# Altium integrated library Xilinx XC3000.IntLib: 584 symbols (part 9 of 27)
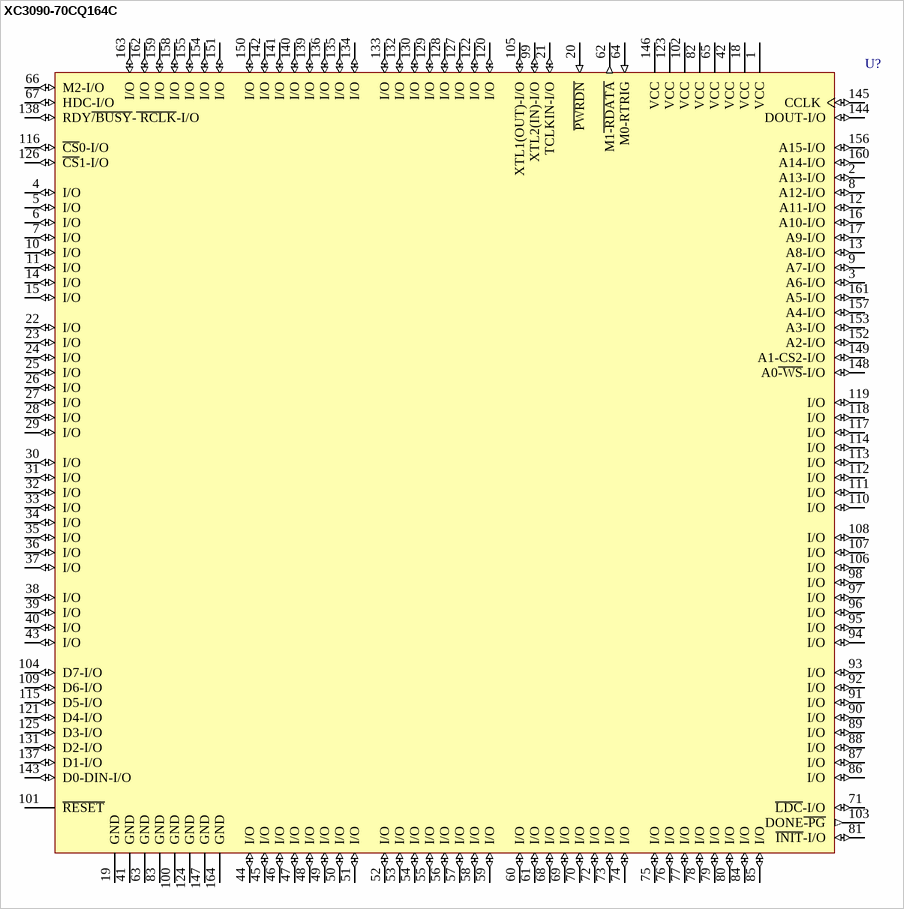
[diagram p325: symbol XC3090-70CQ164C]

## XC3090-70CQ164C
designator U?
Logic Cell Array with 320 CLBs, with 142 I/O Pins, 164-Pin CQFP, Commercial Grade; ComponentAvailability: Not for New Design
footprint CB164_N (CQFP, 164-Leads, Body 29x29mm; Pitch 0.635mm, Gullwing Leadform, IPC Medium Density)
footprint CB164_L (CQFP, 164-Leads, Body 29x29mm; Pitch 0.635mm, Gullwing Leadform, IPC High Density)
footprint CB164_M (CQFP, 164-Leads, Body 29x29mm; Pitch 0.635mm, Gullwing Leadform, IPC Low Density)
3D model XC3090-CB164 (164-Pin Ceramic Brazed Quad Flat Pack (CB164))
pins: 1 VCC (power), 2 A13-I/O (io), 3 A6-I/O (io), 4 I/O (io), 5 I/O (io), 6 I/O (io), 7 I/O (io), 8 A12-I/O (io), 9 A7-I/O (io), 10 I/O (io), 11 I/O (io), 12 A11-I/O (io), 13 A8-I/O (io), 14 I/O (io), 15 I/O (io), 16 A10-I/O (io), 17 A9-I/O (io), 18 VCC (power), 19 GND (power), 20 ~{PWRDN} (in), 21 TCLKIN-I/O (io), 22 I/O (io), 23 I/O (io), 24 I/O (io), 25 I/O (io), 26 I/O (io), 27 I/O (io), 28 I/O (io), 29 I/O (io), 30 I/O (io), 31 I/O (io), 32 I/O (io), 33 I/O (io), 34 I/O (io), 35 I/O (io), 36 I/O (io), 37 I/O (io), 38 I/O (io), 39 I/O (io), 40 I/O (io), 41 GND (power), 42 VCC (power), 43 I/O (io), 44 I/O (io), 45 I/O (io), 46 I/O (io), 47 I/O (io), 48 I/O (io), 49 I/O (io), 50 I/O (io), 51 I/O (io), 52 I/O (io), 53 I/O (io), 54 I/O (io), 55 I/O (io), 56 I/O (io), 57 I/O (io), 58 I/O (io), 59 I/O (io), 60 I/O (io), 61 I/O (io), 62 M1~{-RDATA} (out), 63 GND (power), 64 M0-RTRIG (in), 65 VCC (power), 66 M2-I/O (io), 67 HDC-I/O (io), 68 I/O (io), 69 I/O (io), 70 I/O (io), 71 ~{LDC}-I/O (io), 72 I/O (io), 73 I/O (io), 74 I/O (io), 75 I/O (io), 76 I/O (io), 77 I/O (io), 78 I/O (io), 79 I/O (io), 80 I/O (io), 81 ~{INIT}-I/O (io), 82 VCC (power), 83 GND (power), 84 I/O (io), 85 I/O (io), 86 I/O (io), 87 I/O (io), 88 I/O (io), 89 I/O (io), 90 I/O (io), 91 I/O (io), 92 I/O (io), 93 I/O (io), 94 I/O (io), 95 I/O (io), 96 I/O (io), 97 I/O (io), 98 I/O (io), 99 XTL2(IN)-I/O (io), 100 GND (power), 101 ~{RESET} (oe), 102 VCC (power), 103 DONE~{-PG} (out), 104 D7-I/O (io), 105 XTL1(OUT)-I/O (io), 106 I/O (io), 107 I/O (io), 108 I/O (io), 109 D6-I/O (io), 110 I/O (io), 111 I/O (io), 112 I/O (io), 113 I/O (io), 114 I/O (io), 115 D5-I/O (io), 116 ~{CS}0-I/O (io), 117 I/O (io), 118 I/O (io), 119 I/O (io), 120 I/O (io), 121 D4-I/O (io), 122 I/O (io), 123 VCC (power), 124 GND (power), 125 D3-I/O (io), 126 ~{CS}1-I/O (io), 127 I/O (io), 128 I/O (io), 129 I/O (io), 130 I/O (io), 131 D2-I/O (io), 132 I/O (io), 133 I/O (io), 134 I/O (io), 135 I/O (io), 136 I/O (io), 137 D1-I/O (io), 138 RDY~{/BUSY}-~{ RCLK}-I/O (io), 139 I/O (io), 140 I/O (io), 141 I/O (io), 142 I/O (io), 143 D0-DIN-I/O (io), 144 DOUT-I/O (io), 145 CCLK (io), 146 VCC (power), 147 GND (power), 148 A0~{-WS}-I/O (io), 149 A1-CS2-I/O (io), 150 I/O (io), 151 I/O (io), 152 A2-I/O (io), 153 A3-I/O (io), 154 I/O (io), 155 I/O (io), 156 A15-I/O (io), 157 A4-I/O (io), 158 I/O (io), 159 I/O (io), 160 A14-I/O (io), 161 A5-I/O (io), 162 I/O (io), 163 I/O (io), 164 GND (power)

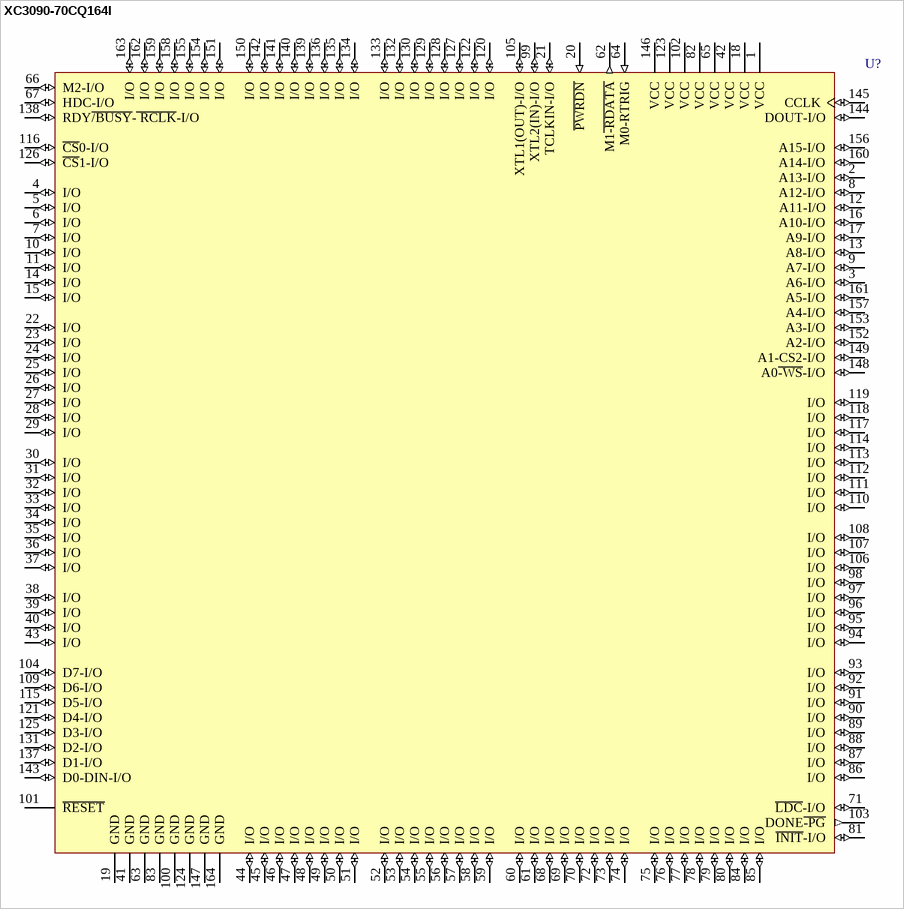
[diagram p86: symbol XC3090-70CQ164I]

## XC3090-70CQ164I
designator U?
Logic Cell Array with 320 CLBs, with 142 I/O Pins, 164-Pin CQFP, Industrial Grade; ComponentAvailability: Not for New Design
footprint CB164_N (CQFP, 164-Leads, Body 29x29mm; Pitch 0.635mm, Gullwing Leadform, IPC Medium Density)
footprint CB164_L (CQFP, 164-Leads, Body 29x29mm; Pitch 0.635mm, Gullwing Leadform, IPC High Density)
footprint CB164_M (CQFP, 164-Leads, Body 29x29mm; Pitch 0.635mm, Gullwing Leadform, IPC Low Density)
3D model XC3090-CB164 (164-Pin Ceramic Brazed Quad Flat Pack (CB164))
pins: 1 VCC (power), 2 A13-I/O (io), 3 A6-I/O (io), 4 I/O (io), 5 I/O (io), 6 I/O (io), 7 I/O (io), 8 A12-I/O (io), 9 A7-I/O (io), 10 I/O (io), 11 I/O (io), 12 A11-I/O (io), 13 A8-I/O (io), 14 I/O (io), 15 I/O (io), 16 A10-I/O (io), 17 A9-I/O (io), 18 VCC (power), 19 GND (power), 20 ~{PWRDN} (in), 21 TCLKIN-I/O (io), 22 I/O (io), 23 I/O (io), 24 I/O (io), 25 I/O (io), 26 I/O (io), 27 I/O (io), 28 I/O (io), 29 I/O (io), 30 I/O (io), 31 I/O (io), 32 I/O (io), 33 I/O (io), 34 I/O (io), 35 I/O (io), 36 I/O (io), 37 I/O (io), 38 I/O (io), 39 I/O (io), 40 I/O (io), 41 GND (power), 42 VCC (power), 43 I/O (io), 44 I/O (io), 45 I/O (io), 46 I/O (io), 47 I/O (io), 48 I/O (io), 49 I/O (io), 50 I/O (io), 51 I/O (io), 52 I/O (io), 53 I/O (io), 54 I/O (io), 55 I/O (io), 56 I/O (io), 57 I/O (io), 58 I/O (io), 59 I/O (io), 60 I/O (io), 61 I/O (io), 62 M1~{-RDATA} (out), 63 GND (power), 64 M0-RTRIG (in), 65 VCC (power), 66 M2-I/O (io), 67 HDC-I/O (io), 68 I/O (io), 69 I/O (io), 70 I/O (io), 71 ~{LDC}-I/O (io), 72 I/O (io), 73 I/O (io), 74 I/O (io), 75 I/O (io), 76 I/O (io), 77 I/O (io), 78 I/O (io), 79 I/O (io), 80 I/O (io), 81 ~{INIT}-I/O (io), 82 VCC (power), 83 GND (power), 84 I/O (io), 85 I/O (io), 86 I/O (io), 87 I/O (io), 88 I/O (io), 89 I/O (io), 90 I/O (io), 91 I/O (io), 92 I/O (io), 93 I/O (io), 94 I/O (io), 95 I/O (io), 96 I/O (io), 97 I/O (io), 98 I/O (io), 99 XTL2(IN)-I/O (io), 100 GND (power), 101 ~{RESET} (oe), 102 VCC (power), 103 DONE~{-PG} (out), 104 D7-I/O (io), 105 XTL1(OUT)-I/O (io), 106 I/O (io), 107 I/O (io), 108 I/O (io), 109 D6-I/O (io), 110 I/O (io), 111 I/O (io), 112 I/O (io), 113 I/O (io), 114 I/O (io), 115 D5-I/O (io), 116 ~{CS}0-I/O (io), 117 I/O (io), 118 I/O (io), 119 I/O (io), 120 I/O (io), 121 D4-I/O (io), 122 I/O (io), 123 VCC (power), 124 GND (power), 125 D3-I/O (io), 126 ~{CS}1-I/O (io), 127 I/O (io), 128 I/O (io), 129 I/O (io), 130 I/O (io), 131 D2-I/O (io), 132 I/O (io), 133 I/O (io), 134 I/O (io), 135 I/O (io), 136 I/O (io), 137 D1-I/O (io), 138 RDY~{/BUSY}-~{ RCLK}-I/O (io), 139 I/O (io), 140 I/O (io), 141 I/O (io), 142 I/O (io), 143 D0-DIN-I/O (io), 144 DOUT-I/O (io), 145 CCLK (io), 146 VCC (power), 147 GND (power), 148 A0~{-WS}-I/O (io), 149 A1-CS2-I/O (io), 150 I/O (io), 151 I/O (io), 152 A2-I/O (io), 153 A3-I/O (io), 154 I/O (io), 155 I/O (io), 156 A15-I/O (io), 157 A4-I/O (io), 158 I/O (io), 159 I/O (io), 160 A14-I/O (io), 161 A5-I/O (io), 162 I/O (io), 163 I/O (io), 164 GND (power)

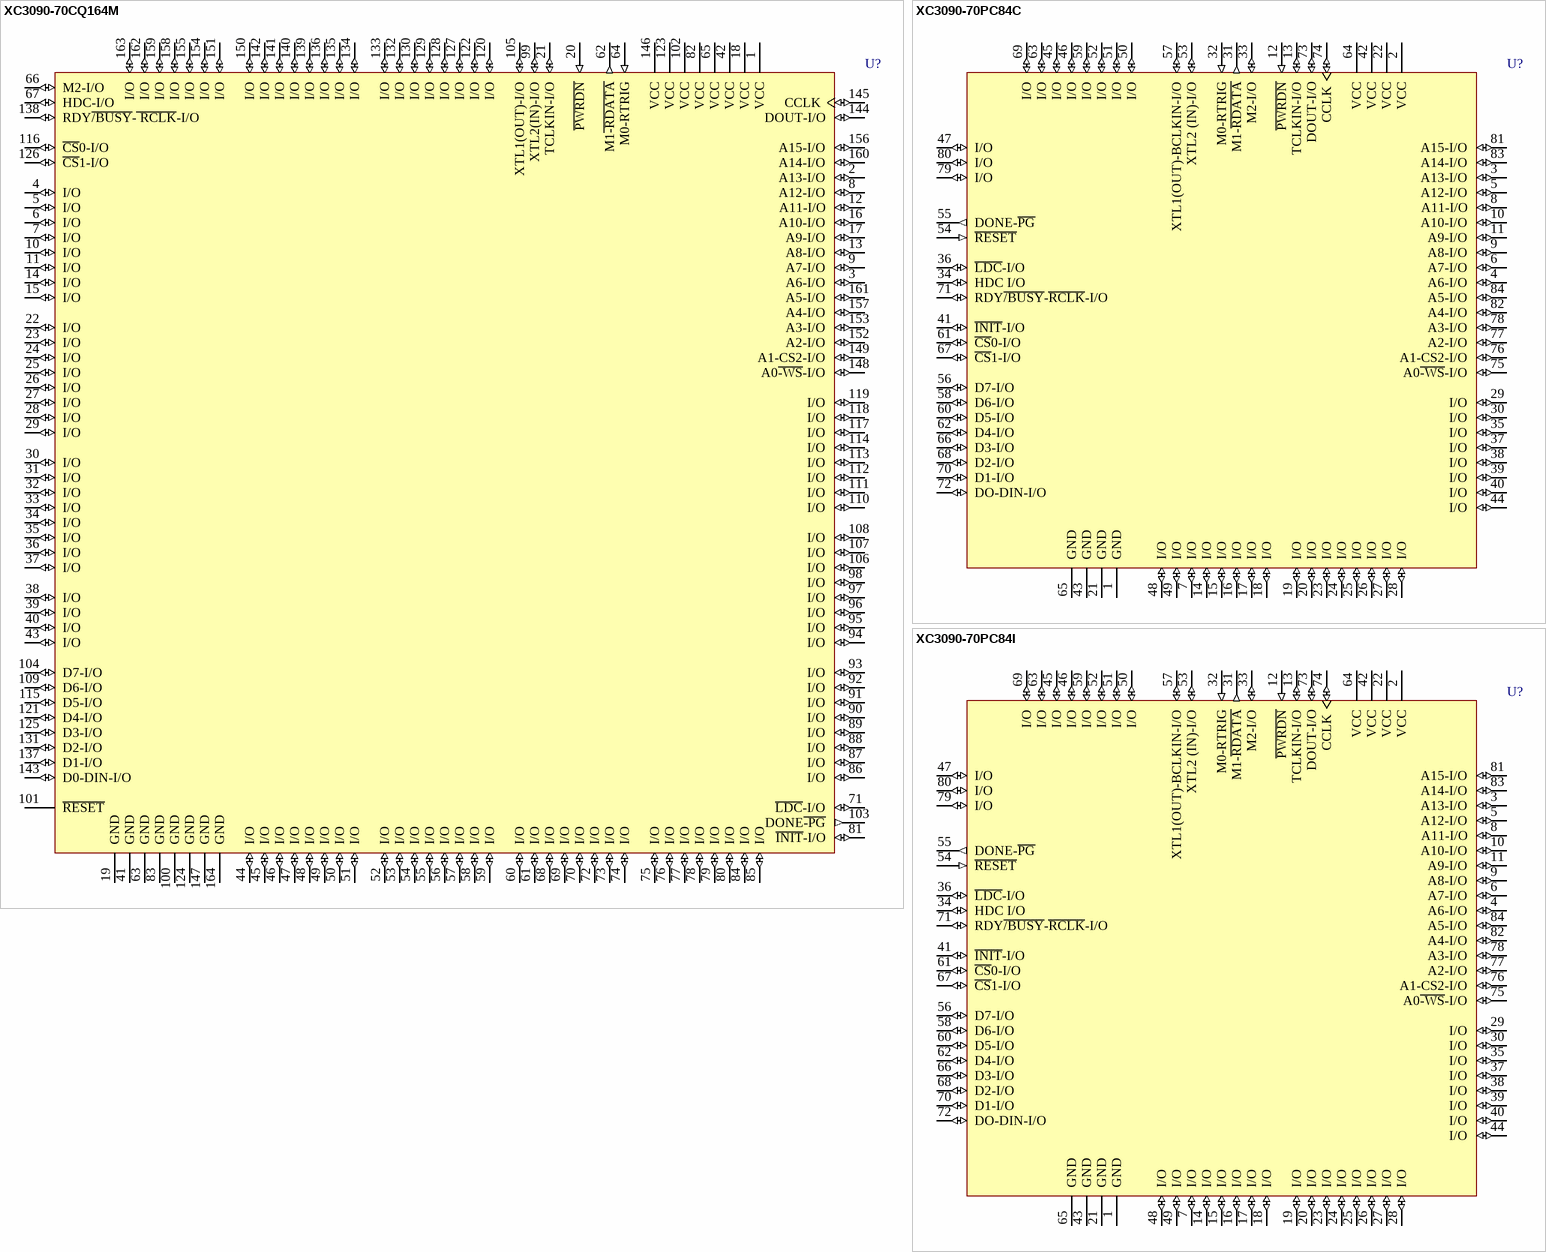
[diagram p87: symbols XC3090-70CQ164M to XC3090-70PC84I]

## XC3090-70CQ164M
designator U?
Logic Cell Array with 320 CLBs, with 142 I/O Pins, 164-Pin CQFP, Military Grade; ComponentAvailability: Not for New Design
footprint CB164_N (CQFP, 164-Leads, Body 29x29mm; Pitch 0.635mm, Gullwing Leadform, IPC Medium Density)
footprint CB164_L (CQFP, 164-Leads, Body 29x29mm; Pitch 0.635mm, Gullwing Leadform, IPC High Density)
footprint CB164_M (CQFP, 164-Leads, Body 29x29mm; Pitch 0.635mm, Gullwing Leadform, IPC Low Density)
3D model XC3090-CB164 (164-Pin Ceramic Brazed Quad Flat Pack (CB164))
pins: 1 VCC (power), 2 A13-I/O (io), 3 A6-I/O (io), 4 I/O (io), 5 I/O (io), 6 I/O (io), 7 I/O (io), 8 A12-I/O (io), 9 A7-I/O (io), 10 I/O (io), 11 I/O (io), 12 A11-I/O (io), 13 A8-I/O (io), 14 I/O (io), 15 I/O (io), 16 A10-I/O (io), 17 A9-I/O (io), 18 VCC (power), 19 GND (power), 20 ~{PWRDN} (in), 21 TCLKIN-I/O (io), 22 I/O (io), 23 I/O (io), 24 I/O (io), 25 I/O (io), 26 I/O (io), 27 I/O (io), 28 I/O (io), 29 I/O (io), 30 I/O (io), 31 I/O (io), 32 I/O (io), 33 I/O (io), 34 I/O (io), 35 I/O (io), 36 I/O (io), 37 I/O (io), 38 I/O (io), 39 I/O (io), 40 I/O (io), 41 GND (power), 42 VCC (power), 43 I/O (io), 44 I/O (io), 45 I/O (io), 46 I/O (io), 47 I/O (io), 48 I/O (io), 49 I/O (io), 50 I/O (io), 51 I/O (io), 52 I/O (io), 53 I/O (io), 54 I/O (io), 55 I/O (io), 56 I/O (io), 57 I/O (io), 58 I/O (io), 59 I/O (io), 60 I/O (io), 61 I/O (io), 62 M1~{-RDATA} (out), 63 GND (power), 64 M0-RTRIG (in), 65 VCC (power), 66 M2-I/O (io), 67 HDC-I/O (io), 68 I/O (io), 69 I/O (io), 70 I/O (io), 71 ~{LDC}-I/O (io), 72 I/O (io), 73 I/O (io), 74 I/O (io), 75 I/O (io), 76 I/O (io), 77 I/O (io), 78 I/O (io), 79 I/O (io), 80 I/O (io), 81 ~{INIT}-I/O (io), 82 VCC (power), 83 GND (power), 84 I/O (io), 85 I/O (io), 86 I/O (io), 87 I/O (io), 88 I/O (io), 89 I/O (io), 90 I/O (io), 91 I/O (io), 92 I/O (io), 93 I/O (io), 94 I/O (io), 95 I/O (io), 96 I/O (io), 97 I/O (io), 98 I/O (io), 99 XTL2(IN)-I/O (io), 100 GND (power), 101 ~{RESET} (oe), 102 VCC (power), 103 DONE~{-PG} (out), 104 D7-I/O (io), 105 XTL1(OUT)-I/O (io), 106 I/O (io), 107 I/O (io), 108 I/O (io), 109 D6-I/O (io), 110 I/O (io), 111 I/O (io), 112 I/O (io), 113 I/O (io), 114 I/O (io), 115 D5-I/O (io), 116 ~{CS}0-I/O (io), 117 I/O (io), 118 I/O (io), 119 I/O (io), 120 I/O (io), 121 D4-I/O (io), 122 I/O (io), 123 VCC (power), 124 GND (power), 125 D3-I/O (io), 126 ~{CS}1-I/O (io), 127 I/O (io), 128 I/O (io), 129 I/O (io), 130 I/O (io), 131 D2-I/O (io), 132 I/O (io), 133 I/O (io), 134 I/O (io), 135 I/O (io), 136 I/O (io), 137 D1-I/O (io), 138 RDY~{/BUSY}-~{ RCLK}-I/O (io), 139 I/O (io), 140 I/O (io), 141 I/O (io), 142 I/O (io), 143 D0-DIN-I/O (io), 144 DOUT-I/O (io), 145 CCLK (io), 146 VCC (power), 147 GND (power), 148 A0~{-WS}-I/O (io), 149 A1-CS2-I/O (io), 150 I/O (io), 151 I/O (io), 152 A2-I/O (io), 153 A3-I/O (io), 154 I/O (io), 155 I/O (io), 156 A15-I/O (io), 157 A4-I/O (io), 158 I/O (io), 159 I/O (io), 160 A14-I/O (io), 161 A5-I/O (io), 162 I/O (io), 163 I/O (io), 164 GND (power)

## XC3090-70PC84C
designator U?
Logic Cell Array with 320 CLBs, with 70 I/O Pins, 84-Pin PLCC, Commercial Grade; ComponentAvailability: Not for New Design
footprint PC84_N (Leaded Chip Carrier, 84-Leads, Body 29.3x29.3mm, Pitch 1.27mm, IPC Medium Density)
footprint PC84_L (Leaded Chip Carrier, 84-Leads, Body 29.3x29.3mm, Pitch 1.27mm, IPC High Density)
footprint PC84_M (Leaded Chip Carrier, 84-Leads, Body 29.3x29.3mm, Pitch 1.27mm, IPC Low Density)
3D model XC3090-PC84 (84-Pin Plastic Leaded Chip Carrier (PC84))
pins: 1 GND (power), 2 VCC (power), 3 A13-I/O (io), 4 A6-I/O (io), 5 A12-I/O (io), 6 A7-I/O (io), 7 I/O (io), 8 A11-I/O (io), 9 A8-I/O (io), 10 A10-I/O (io), 11 A9-I/O (io), 12 ~{PWRDN} (in), 13 TCLKIN-I/O (io), 14 I/O (io), 15 I/O (io), 16 I/O (io), 17 I/O (io), 18 I/O (io), 19 I/O (io), 20 I/O (io), 21 GND (power), 22 VCC (power), 23 I/O (io), 24 I/O (io), 25 I/O (io), 26 I/O (io), 27 I/O (io), 28 I/O (io), 29 I/O (io), 30 I/O (io), 31 M1-~{RDATA} (out), 32 M0-RTRIG (in), 33 M2-I/O (io), 34 HDC I/O (io), 35 I/O (io), 36 ~{LDC}-I/O (io), 37 I/O (io), 38 I/O (io), 39 I/O (io), 40 I/O (io), 41 ~{INIT}-I/O (io), 42 VCC (power), 43 GND (power), 44 I/O (io), 45 I/O (io), 46 I/O (io), 47 I/O (io), 48 I/O (io), 49 I/O (io), 50 I/O (io), 51 I/O (io), 52 I/O (io), 53 XTL2 (IN)-I/O (io), 54 ~{RESET} (in), 55 DONE-~{PG} (out), 56 D7-I/O (io), 57 XTL1(OUT)-BCLKIN-I/O (io), 58 D6-I/O (io), 59 I/O (io), 60 D5-I/O (io), 61 ~{CS}0-I/O (io), 62 D4-I/O (io), 63 I/O (io), 64 VCC (power), 65 GND (power), 66 D3-I/O (io), 67 ~{CS}1-I/O (io), 68 D2-I/O (io), 69 I/O (io), 70 D1-I/O (io), 71 RDY~{/BUSY}-~{RCLK}-I/O (io), 72 DO-DIN-I/O (io), 73 DOUT-I/O (io), 74 CCLK (io), 75 A0~{-WS}-I/O (io), 76 A1-CS2-I/O (io), 77 A2-I/O (io), 78 A3-I/O (io), 79 I/O (io), 80 I/O (io), 81 A15-I/O (io), 82 A4-I/O (io), 83 A14-I/O (io), 84 A5-I/O (io)

## XC3090-70PC84I
designator U?
Logic Cell Array with 320 CLBs, with 70 I/O Pins, 84-Pin PLCC, Industrial Grade; ComponentAvailability: Not for New Design
footprint PC84_N (Leaded Chip Carrier, 84-Leads, Body 29.3x29.3mm, Pitch 1.27mm, IPC Medium Density)
footprint PC84_L (Leaded Chip Carrier, 84-Leads, Body 29.3x29.3mm, Pitch 1.27mm, IPC High Density)
footprint PC84_M (Leaded Chip Carrier, 84-Leads, Body 29.3x29.3mm, Pitch 1.27mm, IPC Low Density)
3D model XC3090-PC84 (84-Pin Plastic Leaded Chip Carrier (PC84))
pins: 1 GND (power), 2 VCC (power), 3 A13-I/O (io), 4 A6-I/O (io), 5 A12-I/O (io), 6 A7-I/O (io), 7 I/O (io), 8 A11-I/O (io), 9 A8-I/O (io), 10 A10-I/O (io), 11 A9-I/O (io), 12 ~{PWRDN} (in), 13 TCLKIN-I/O (io), 14 I/O (io), 15 I/O (io), 16 I/O (io), 17 I/O (io), 18 I/O (io), 19 I/O (io), 20 I/O (io), 21 GND (power), 22 VCC (power), 23 I/O (io), 24 I/O (io), 25 I/O (io), 26 I/O (io), 27 I/O (io), 28 I/O (io), 29 I/O (io), 30 I/O (io), 31 M1-~{RDATA} (out), 32 M0-RTRIG (in), 33 M2-I/O (io), 34 HDC I/O (io), 35 I/O (io), 36 ~{LDC}-I/O (io), 37 I/O (io), 38 I/O (io), 39 I/O (io), 40 I/O (io), 41 ~{INIT}-I/O (io), 42 VCC (power), 43 GND (power), 44 I/O (io), 45 I/O (io), 46 I/O (io), 47 I/O (io), 48 I/O (io), 49 I/O (io), 50 I/O (io), 51 I/O (io), 52 I/O (io), 53 XTL2 (IN)-I/O (io), 54 ~{RESET} (in), 55 DONE-~{PG} (out), 56 D7-I/O (io), 57 XTL1(OUT)-BCLKIN-I/O (io), 58 D6-I/O (io), 59 I/O (io), 60 D5-I/O (io), 61 ~{CS}0-I/O (io), 62 D4-I/O (io), 63 I/O (io), 64 VCC (power), 65 GND (power), 66 D3-I/O (io), 67 ~{CS}1-I/O (io), 68 D2-I/O (io), 69 I/O (io), 70 D1-I/O (io), 71 RDY~{/BUSY}-~{RCLK}-I/O (io), 72 DO-DIN-I/O (io), 73 DOUT-I/O (io), 74 CCLK (io), 75 A0~{-WS}-I/O (io), 76 A1-CS2-I/O (io), 77 A2-I/O (io), 78 A3-I/O (io), 79 I/O (io), 80 I/O (io), 81 A15-I/O (io), 82 A4-I/O (io), 83 A14-I/O (io), 84 A5-I/O (io)

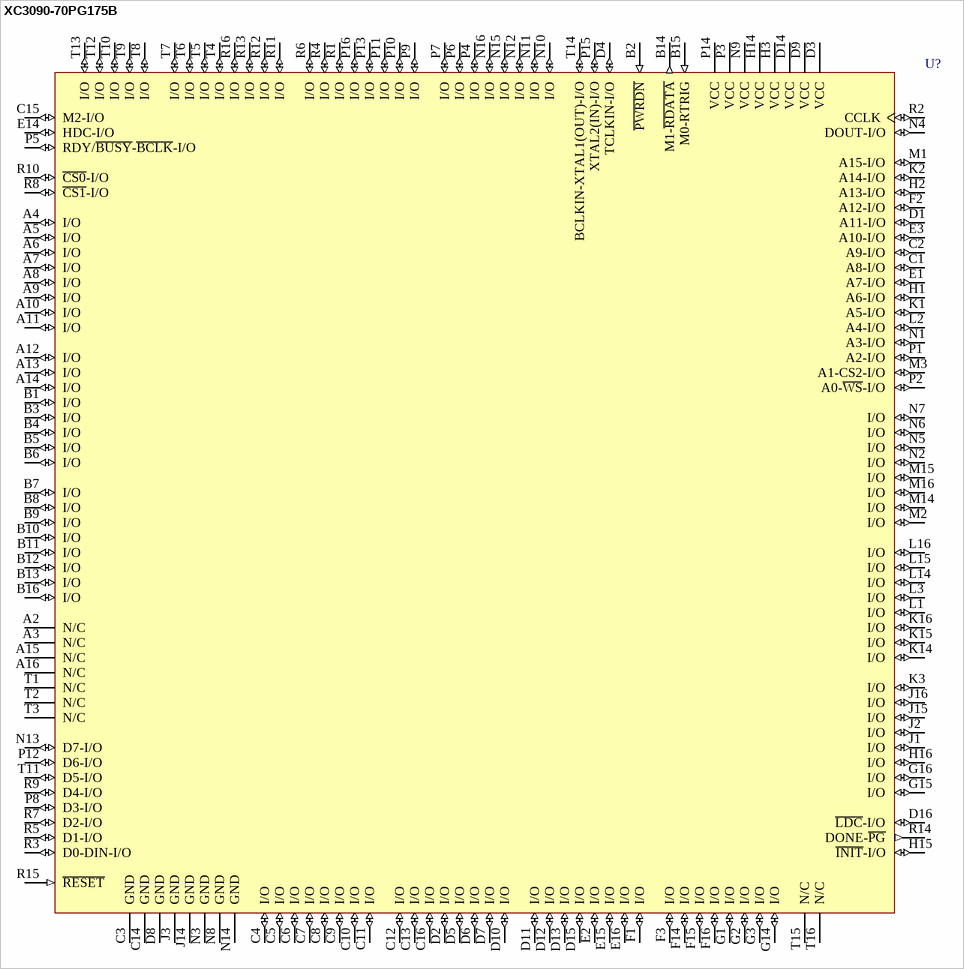
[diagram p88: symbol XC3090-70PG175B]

## XC3090-70PG175B
designator U?
Logic Cell Array with 320 CLBs, with 144 I/O Pins, 175-Pin PGA, Military Class B Grade; ComponentAvailability: Not for New Design
footprint PG175 (PGA, 175-Leads, Body 42x42mm, Pitch 2.54mm)
3D model XC3090-PG175 (175-Pin Ceramic Pin Grid Array (PG175))
pins: A2 N/C, A3 N/C, A4 I/O (io), A5 I/O (io), A6 I/O (io), A7 I/O (io), A8 I/O (io), A9 I/O (io), A10 I/O (io), A11 I/O (io), A12 I/O (io), A13 I/O (io), A14 I/O (io), A15 N/C, A16 N/C, B1 I/O (io), B2 ~{PWRDN} (in), B3 I/O (io), B4 I/O (io), B5 I/O (io), B6 I/O (io), B7 I/O (io), B8 I/O (io), B9 I/O (io), B10 I/O (io), B11 I/O (io), B12 I/O (io), B13 I/O (io), B14 M1-~{RDATA} (out), B15 M0-RTRIG (in), B16 I/O (io), C1 A8-I/O (io), C2 A9-I/O (io), C3 GND (power), C4 I/O (io), C5 I/O (io), C6 I/O (io), C7 I/O (io), C8 I/O (io), C9 I/O (io), C10 I/O (io), C11 I/O (io), C12 I/O (io), C13 I/O (io), C14 GND (power), C15 M2-I/O (io), C16 I/O (io), D1 A11-I/O (io), D2 I/O (io), D3 VCC (power), D4 TCLKIN-I/O (io), D5 I/O (io), D6 I/O (io), D7 I/O (io), D8 GND (power), D9 VCC (power), D10 I/O (io), D11 I/O (io), D12 I/O (io), D13 I/O (io), D14 VCC (power), D15 I/O (io), D16 ~{LDC}-I/O (io), E1 A7-I/O (io), E2 I/O (io), E3 A10-I/O (io), E14 HDC-I/O (io), E15 I/O (io), E16 I/O (io), F1 I/O (io), F2 A12-I/O (io), F3 I/O (io), F14 I/O (io), F15 I/O (io), F16 I/O (io), G1 I/O (io), G2 I/O (io), G3 I/O (io), G14 I/O (io), G15 I/O (io), G16 I/O (io), H1 A6-I/O (io), H2 A13-I/O (io), H3 VCC (power), H14 VCC (power), H15 ~{INIT}-I/O (io), H16 I/O (io), J1 I/O (io), J2 I/O (io), J3 GND (power), J14 GND (power), J15 I/O (io), J16 I/O (io), K1 A5-I/O (io), K2 A14-I/O (io), K3 I/O (io), K14 I/O (io), K15 I/O (io), K16 I/O (io), L1 I/O (io), L2 A4-I/O (io), L3 I/O (io), L14 I/O (io), L15 I/O (io), L16 I/O (io), M1 A15-I/O (io), M2 I/O (io), M3 A1-CS2-I/O (io), M14 I/O (io), M15 I/O (io), M16 I/O (io), N1 A3-I/O (io), N2 I/O (io), N3 GND (power), N4 DOUT-I/O (io), N5 I/O (io), N6 I/O (io), N7 I/O (io), N8 GND (power), N9 VCC (power), N10 I/O (io), N11 I/O (io), N12 I/O (io), N13 D7-I/O (io), N14 GND (power), N15 I/O (io), N16 I/O (io), P1 A2-I/O (io), P2 A0-~{WS}-I/O (io), P3 VCC (power), P4 I/O (io), P5 RDY/~{BUSY}-~{BCLK}-I/O (io), P6 I/O (io), P7 I/O (io), P8 D3-I/O (io), P9 I/O (io), P10 I/O (io), P11 I/O (io), P12 D6-I/O (io), P13 I/O (io), P14 VCC (power), P15 XTAL2(IN)-I/O (io), P16 I/O (io), R1 I/O (io), R2 CCLK (io), R3 D0-DIN-I/O (io), R4 I/O (io), R5 D1-I/O (io), R6 I/O (io), R7 D2-I/O (io), R8 ~{CS1}-I/O (io), R9 D4-I/O (io), R10 ~{CS0}-I/O (io), R11 I/O (io), R12 I/O (io), R13 I/O (io), R14 DONE-~{PG} (out), R15 ~{RESET} (in), R16 I/O (io), T1 N/C, T2 N/C, T3 N/C, T4 I/O (io), T5 I/O (io), T6 I/O (io), T7 I/O (io), T8 I/O (io), T9 I/O (io), T10 I/O (io), T11 D5-I/O (io), T12 I/O (io), T13 I/O (io), T14 BCLKIN-XTAL1(OUT)-I/O (io), T15 N/C, T16 N/C

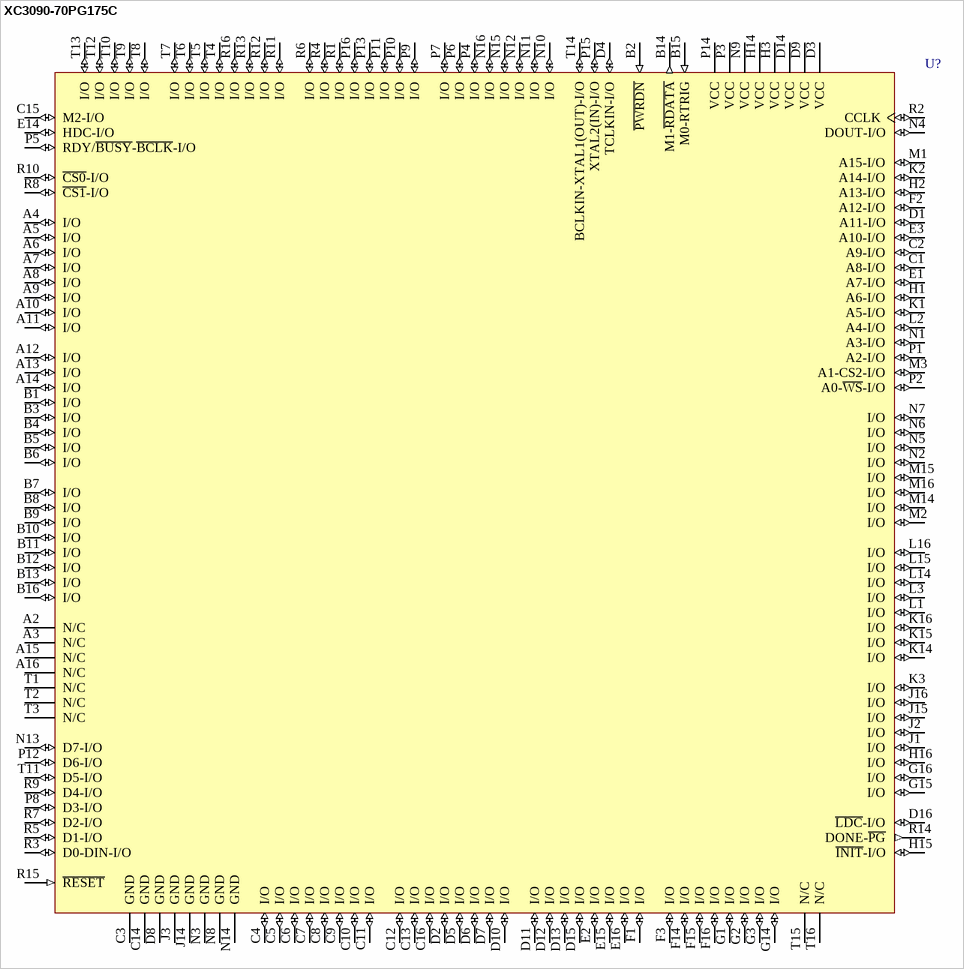
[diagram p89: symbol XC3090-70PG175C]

## XC3090-70PG175C
designator U?
Logic Cell Array with 320 CLBs, with 144 I/O Pins, 175-Pin PGA, Commercial Grade; ComponentAvailability: Not for New Design
footprint PG175 (PGA, 175-Leads, Body 42x42mm, Pitch 2.54mm)
3D model XC3090-PG175 (175-Pin Ceramic Pin Grid Array (PG175))
pins: A2 N/C, A3 N/C, A4 I/O (io), A5 I/O (io), A6 I/O (io), A7 I/O (io), A8 I/O (io), A9 I/O (io), A10 I/O (io), A11 I/O (io), A12 I/O (io), A13 I/O (io), A14 I/O (io), A15 N/C, A16 N/C, B1 I/O (io), B2 ~{PWRDN} (in), B3 I/O (io), B4 I/O (io), B5 I/O (io), B6 I/O (io), B7 I/O (io), B8 I/O (io), B9 I/O (io), B10 I/O (io), B11 I/O (io), B12 I/O (io), B13 I/O (io), B14 M1-~{RDATA} (out), B15 M0-RTRIG (in), B16 I/O (io), C1 A8-I/O (io), C2 A9-I/O (io), C3 GND (power), C4 I/O (io), C5 I/O (io), C6 I/O (io), C7 I/O (io), C8 I/O (io), C9 I/O (io), C10 I/O (io), C11 I/O (io), C12 I/O (io), C13 I/O (io), C14 GND (power), C15 M2-I/O (io), C16 I/O (io), D1 A11-I/O (io), D2 I/O (io), D3 VCC (power), D4 TCLKIN-I/O (io), D5 I/O (io), D6 I/O (io), D7 I/O (io), D8 GND (power), D9 VCC (power), D10 I/O (io), D11 I/O (io), D12 I/O (io), D13 I/O (io), D14 VCC (power), D15 I/O (io), D16 ~{LDC}-I/O (io), E1 A7-I/O (io), E2 I/O (io), E3 A10-I/O (io), E14 HDC-I/O (io), E15 I/O (io), E16 I/O (io), F1 I/O (io), F2 A12-I/O (io), F3 I/O (io), F14 I/O (io), F15 I/O (io), F16 I/O (io), G1 I/O (io), G2 I/O (io), G3 I/O (io), G14 I/O (io), G15 I/O (io), G16 I/O (io), H1 A6-I/O (io), H2 A13-I/O (io), H3 VCC (power), H14 VCC (power), H15 ~{INIT}-I/O (io), H16 I/O (io), J1 I/O (io), J2 I/O (io), J3 GND (power), J14 GND (power), J15 I/O (io), J16 I/O (io), K1 A5-I/O (io), K2 A14-I/O (io), K3 I/O (io), K14 I/O (io), K15 I/O (io), K16 I/O (io), L1 I/O (io), L2 A4-I/O (io), L3 I/O (io), L14 I/O (io), L15 I/O (io), L16 I/O (io), M1 A15-I/O (io), M2 I/O (io), M3 A1-CS2-I/O (io), M14 I/O (io), M15 I/O (io), M16 I/O (io), N1 A3-I/O (io), N2 I/O (io), N3 GND (power), N4 DOUT-I/O (io), N5 I/O (io), N6 I/O (io), N7 I/O (io), N8 GND (power), N9 VCC (power), N10 I/O (io), N11 I/O (io), N12 I/O (io), N13 D7-I/O (io), N14 GND (power), N15 I/O (io), N16 I/O (io), P1 A2-I/O (io), P2 A0-~{WS}-I/O (io), P3 VCC (power), P4 I/O (io), P5 RDY/~{BUSY}-~{BCLK}-I/O (io), P6 I/O (io), P7 I/O (io), P8 D3-I/O (io), P9 I/O (io), P10 I/O (io), P11 I/O (io), P12 D6-I/O (io), P13 I/O (io), P14 VCC (power), P15 XTAL2(IN)-I/O (io), P16 I/O (io), R1 I/O (io), R2 CCLK (io), R3 D0-DIN-I/O (io), R4 I/O (io), R5 D1-I/O (io), R6 I/O (io), R7 D2-I/O (io), R8 ~{CS1}-I/O (io), R9 D4-I/O (io), R10 ~{CS0}-I/O (io), R11 I/O (io), R12 I/O (io), R13 I/O (io), R14 DONE-~{PG} (out), R15 ~{RESET} (in), R16 I/O (io), T1 N/C, T2 N/C, T3 N/C, T4 I/O (io), T5 I/O (io), T6 I/O (io), T7 I/O (io), T8 I/O (io), T9 I/O (io), T10 I/O (io), T11 D5-I/O (io), T12 I/O (io), T13 I/O (io), T14 BCLKIN-XTAL1(OUT)-I/O (io), T15 N/C, T16 N/C

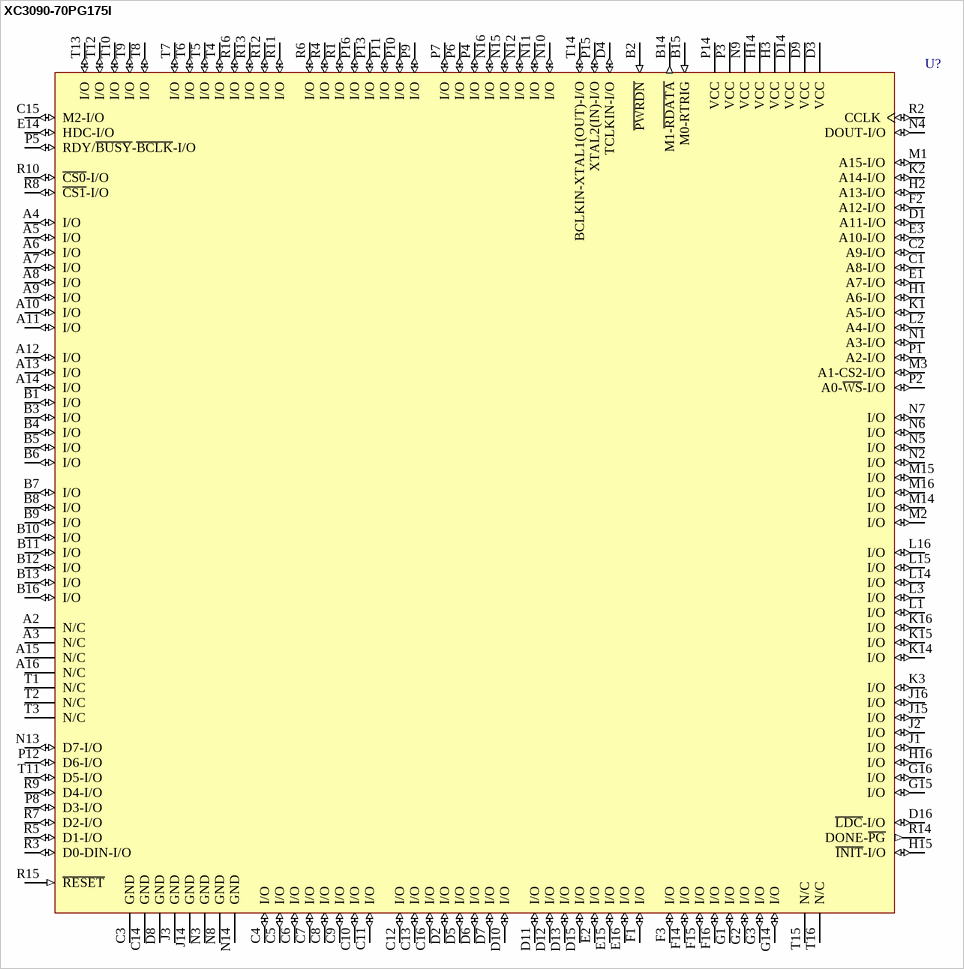
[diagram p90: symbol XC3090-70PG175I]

## XC3090-70PG175I
designator U?
Logic Cell Array with 320 CLBs, with 144 I/O Pins, 175-Pin PGA, Industrial Grade; ComponentAvailability: Not for New Design
footprint PG175 (PGA, 175-Leads, Body 42x42mm, Pitch 2.54mm)
3D model XC3090-PG175 (175-Pin Ceramic Pin Grid Array (PG175))
pins: A2 N/C, A3 N/C, A4 I/O (io), A5 I/O (io), A6 I/O (io), A7 I/O (io), A8 I/O (io), A9 I/O (io), A10 I/O (io), A11 I/O (io), A12 I/O (io), A13 I/O (io), A14 I/O (io), A15 N/C, A16 N/C, B1 I/O (io), B2 ~{PWRDN} (in), B3 I/O (io), B4 I/O (io), B5 I/O (io), B6 I/O (io), B7 I/O (io), B8 I/O (io), B9 I/O (io), B10 I/O (io), B11 I/O (io), B12 I/O (io), B13 I/O (io), B14 M1-~{RDATA} (out), B15 M0-RTRIG (in), B16 I/O (io), C1 A8-I/O (io), C2 A9-I/O (io), C3 GND (power), C4 I/O (io), C5 I/O (io), C6 I/O (io), C7 I/O (io), C8 I/O (io), C9 I/O (io), C10 I/O (io), C11 I/O (io), C12 I/O (io), C13 I/O (io), C14 GND (power), C15 M2-I/O (io), C16 I/O (io), D1 A11-I/O (io), D2 I/O (io), D3 VCC (power), D4 TCLKIN-I/O (io), D5 I/O (io), D6 I/O (io), D7 I/O (io), D8 GND (power), D9 VCC (power), D10 I/O (io), D11 I/O (io), D12 I/O (io), D13 I/O (io), D14 VCC (power), D15 I/O (io), D16 ~{LDC}-I/O (io), E1 A7-I/O (io), E2 I/O (io), E3 A10-I/O (io), E14 HDC-I/O (io), E15 I/O (io), E16 I/O (io), F1 I/O (io), F2 A12-I/O (io), F3 I/O (io), F14 I/O (io), F15 I/O (io), F16 I/O (io), G1 I/O (io), G2 I/O (io), G3 I/O (io), G14 I/O (io), G15 I/O (io), G16 I/O (io), H1 A6-I/O (io), H2 A13-I/O (io), H3 VCC (power), H14 VCC (power), H15 ~{INIT}-I/O (io), H16 I/O (io), J1 I/O (io), J2 I/O (io), J3 GND (power), J14 GND (power), J15 I/O (io), J16 I/O (io), K1 A5-I/O (io), K2 A14-I/O (io), K3 I/O (io), K14 I/O (io), K15 I/O (io), K16 I/O (io), L1 I/O (io), L2 A4-I/O (io), L3 I/O (io), L14 I/O (io), L15 I/O (io), L16 I/O (io), M1 A15-I/O (io), M2 I/O (io), M3 A1-CS2-I/O (io), M14 I/O (io), M15 I/O (io), M16 I/O (io), N1 A3-I/O (io), N2 I/O (io), N3 GND (power), N4 DOUT-I/O (io), N5 I/O (io), N6 I/O (io), N7 I/O (io), N8 GND (power), N9 VCC (power), N10 I/O (io), N11 I/O (io), N12 I/O (io), N13 D7-I/O (io), N14 GND (power), N15 I/O (io), N16 I/O (io), P1 A2-I/O (io), P2 A0-~{WS}-I/O (io), P3 VCC (power), P4 I/O (io), P5 RDY/~{BUSY}-~{BCLK}-I/O (io), P6 I/O (io), P7 I/O (io), P8 D3-I/O (io), P9 I/O (io), P10 I/O (io), P11 I/O (io), P12 D6-I/O (io), P13 I/O (io), P14 VCC (power), P15 XTAL2(IN)-I/O (io), P16 I/O (io), R1 I/O (io), R2 CCLK (io), R3 D0-DIN-I/O (io), R4 I/O (io), R5 D1-I/O (io), R6 I/O (io), R7 D2-I/O (io), R8 ~{CS1}-I/O (io), R9 D4-I/O (io), R10 ~{CS0}-I/O (io), R11 I/O (io), R12 I/O (io), R13 I/O (io), R14 DONE-~{PG} (out), R15 ~{RESET} (in), R16 I/O (io), T1 N/C, T2 N/C, T3 N/C, T4 I/O (io), T5 I/O (io), T6 I/O (io), T7 I/O (io), T8 I/O (io), T9 I/O (io), T10 I/O (io), T11 D5-I/O (io), T12 I/O (io), T13 I/O (io), T14 BCLKIN-XTAL1(OUT)-I/O (io), T15 N/C, T16 N/C

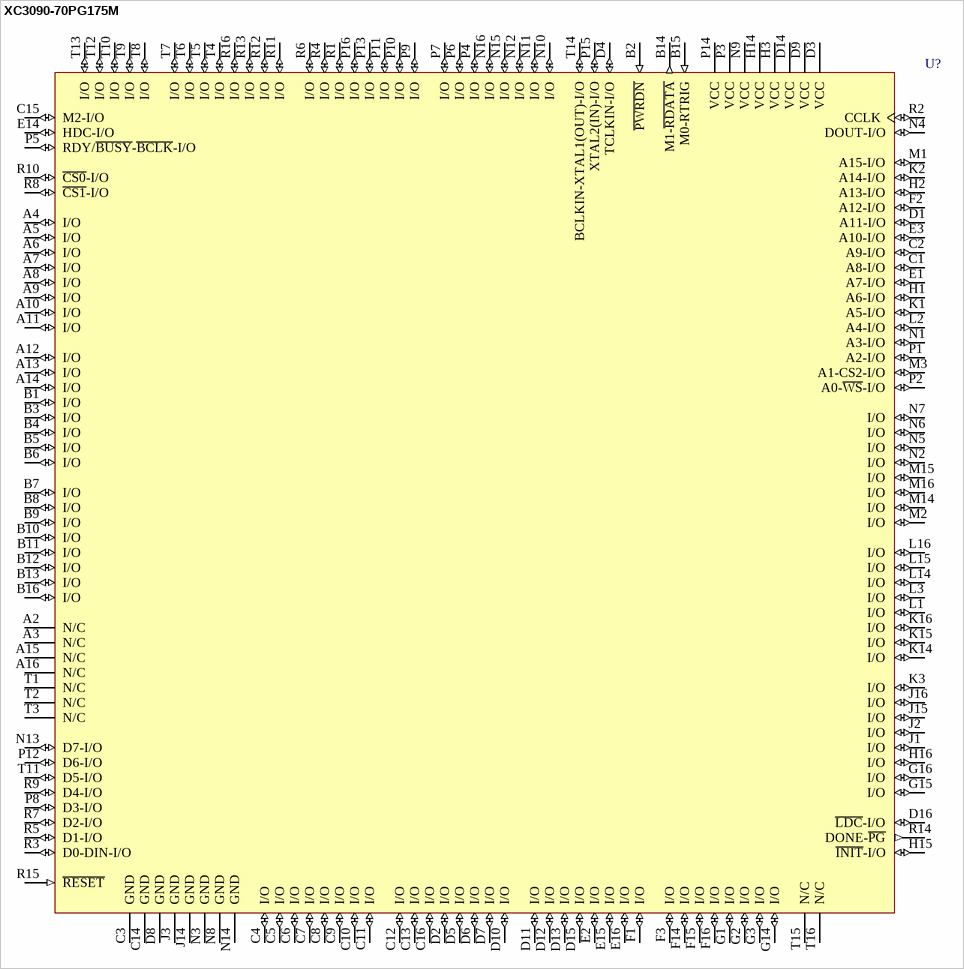
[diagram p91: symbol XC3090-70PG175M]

## XC3090-70PG175M
designator U?
Logic Cell Array with 320 CLBs, with 144 I/O Pins, 175-Pin PGA, Military Grade; ComponentAvailability: Not for New Design
footprint PG175 (PGA, 175-Leads, Body 42x42mm, Pitch 2.54mm)
3D model XC3090-PG175 (175-Pin Ceramic Pin Grid Array (PG175))
pins: A2 N/C, A3 N/C, A4 I/O (io), A5 I/O (io), A6 I/O (io), A7 I/O (io), A8 I/O (io), A9 I/O (io), A10 I/O (io), A11 I/O (io), A12 I/O (io), A13 I/O (io), A14 I/O (io), A15 N/C, A16 N/C, B1 I/O (io), B2 ~{PWRDN} (in), B3 I/O (io), B4 I/O (io), B5 I/O (io), B6 I/O (io), B7 I/O (io), B8 I/O (io), B9 I/O (io), B10 I/O (io), B11 I/O (io), B12 I/O (io), B13 I/O (io), B14 M1-~{RDATA} (out), B15 M0-RTRIG (in), B16 I/O (io), C1 A8-I/O (io), C2 A9-I/O (io), C3 GND (power), C4 I/O (io), C5 I/O (io), C6 I/O (io), C7 I/O (io), C8 I/O (io), C9 I/O (io), C10 I/O (io), C11 I/O (io), C12 I/O (io), C13 I/O (io), C14 GND (power), C15 M2-I/O (io), C16 I/O (io), D1 A11-I/O (io), D2 I/O (io), D3 VCC (power), D4 TCLKIN-I/O (io), D5 I/O (io), D6 I/O (io), D7 I/O (io), D8 GND (power), D9 VCC (power), D10 I/O (io), D11 I/O (io), D12 I/O (io), D13 I/O (io), D14 VCC (power), D15 I/O (io), D16 ~{LDC}-I/O (io), E1 A7-I/O (io), E2 I/O (io), E3 A10-I/O (io), E14 HDC-I/O (io), E15 I/O (io), E16 I/O (io), F1 I/O (io), F2 A12-I/O (io), F3 I/O (io), F14 I/O (io), F15 I/O (io), F16 I/O (io), G1 I/O (io), G2 I/O (io), G3 I/O (io), G14 I/O (io), G15 I/O (io), G16 I/O (io), H1 A6-I/O (io), H2 A13-I/O (io), H3 VCC (power), H14 VCC (power), H15 ~{INIT}-I/O (io), H16 I/O (io), J1 I/O (io), J2 I/O (io), J3 GND (power), J14 GND (power), J15 I/O (io), J16 I/O (io), K1 A5-I/O (io), K2 A14-I/O (io), K3 I/O (io), K14 I/O (io), K15 I/O (io), K16 I/O (io), L1 I/O (io), L2 A4-I/O (io), L3 I/O (io), L14 I/O (io), L15 I/O (io), L16 I/O (io), M1 A15-I/O (io), M2 I/O (io), M3 A1-CS2-I/O (io), M14 I/O (io), M15 I/O (io), M16 I/O (io), N1 A3-I/O (io), N2 I/O (io), N3 GND (power), N4 DOUT-I/O (io), N5 I/O (io), N6 I/O (io), N7 I/O (io), N8 GND (power), N9 VCC (power), N10 I/O (io), N11 I/O (io), N12 I/O (io), N13 D7-I/O (io), N14 GND (power), N15 I/O (io), N16 I/O (io), P1 A2-I/O (io), P2 A0-~{WS}-I/O (io), P3 VCC (power), P4 I/O (io), P5 RDY/~{BUSY}-~{BCLK}-I/O (io), P6 I/O (io), P7 I/O (io), P8 D3-I/O (io), P9 I/O (io), P10 I/O (io), P11 I/O (io), P12 D6-I/O (io), P13 I/O (io), P14 VCC (power), P15 XTAL2(IN)-I/O (io), P16 I/O (io), R1 I/O (io), R2 CCLK (io), R3 D0-DIN-I/O (io), R4 I/O (io), R5 D1-I/O (io), R6 I/O (io), R7 D2-I/O (io), R8 ~{CS1}-I/O (io), R9 D4-I/O (io), R10 ~{CS0}-I/O (io), R11 I/O (io), R12 I/O (io), R13 I/O (io), R14 DONE-~{PG} (out), R15 ~{RESET} (in), R16 I/O (io), T1 N/C, T2 N/C, T3 N/C, T4 I/O (io), T5 I/O (io), T6 I/O (io), T7 I/O (io), T8 I/O (io), T9 I/O (io), T10 I/O (io), T11 D5-I/O (io), T12 I/O (io), T13 I/O (io), T14 BCLKIN-XTAL1(OUT)-I/O (io), T15 N/C, T16 N/C

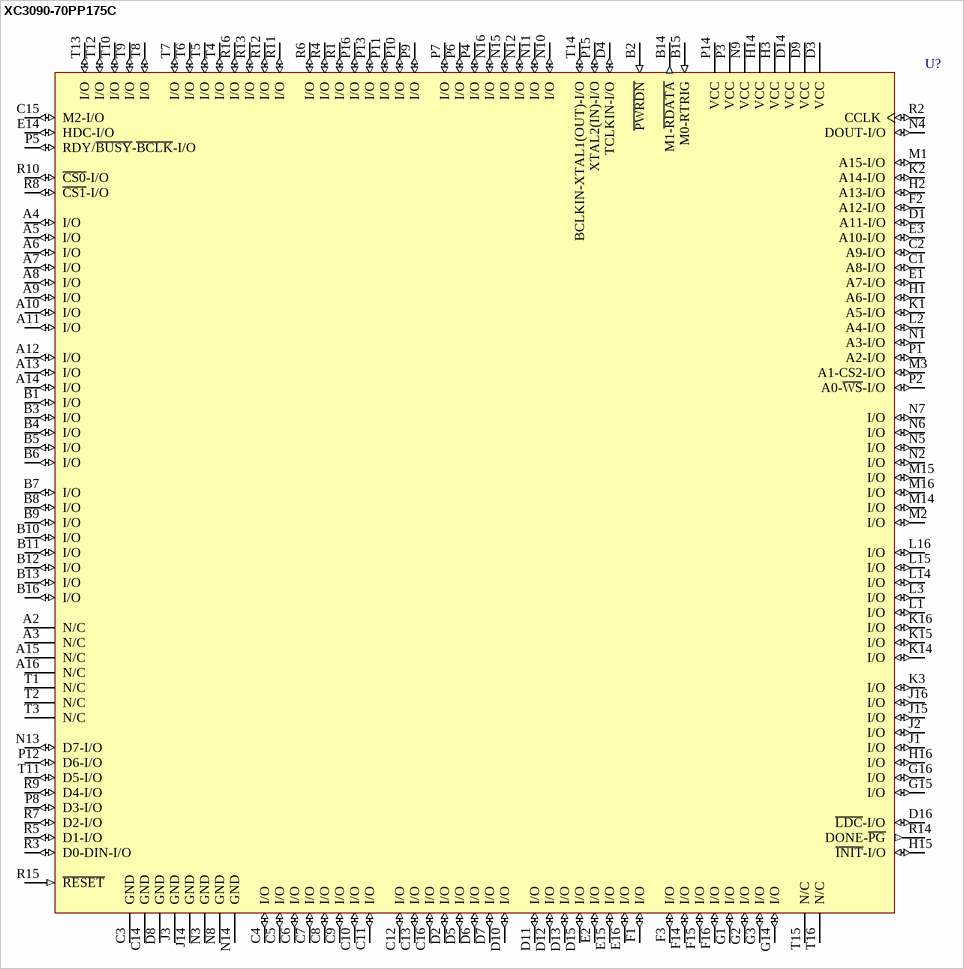
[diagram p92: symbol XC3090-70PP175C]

## XC3090-70PP175C
designator U?
Logic Cell Array with 320 CLBs, with 144 I/O Pins, 175-Pin PGA, Commercial Grade; ComponentAvailability: Not for New Design
footprint PP175 (PGA, 175-Leads, Body 42x42mm, Pitch 2.54mm)
3D model XC3090-PP175 (175-Pin Plastic Pin Grid Array (PP175))
pins: A2 N/C, A3 N/C, A4 I/O (io), A5 I/O (io), A6 I/O (io), A7 I/O (io), A8 I/O (io), A9 I/O (io), A10 I/O (io), A11 I/O (io), A12 I/O (io), A13 I/O (io), A14 I/O (io), A15 N/C, A16 N/C, B1 I/O (io), B2 ~{PWRDN} (in), B3 I/O (io), B4 I/O (io), B5 I/O (io), B6 I/O (io), B7 I/O (io), B8 I/O (io), B9 I/O (io), B10 I/O (io), B11 I/O (io), B12 I/O (io), B13 I/O (io), B14 M1-~{RDATA} (out), B15 M0-RTRIG (in), B16 I/O (io), C1 A8-I/O (io), C2 A9-I/O (io), C3 GND (power), C4 I/O (io), C5 I/O (io), C6 I/O (io), C7 I/O (io), C8 I/O (io), C9 I/O (io), C10 I/O (io), C11 I/O (io), C12 I/O (io), C13 I/O (io), C14 GND (power), C15 M2-I/O (io), C16 I/O (io), D1 A11-I/O (io), D2 I/O (io), D3 VCC (power), D4 TCLKIN-I/O (io), D5 I/O (io), D6 I/O (io), D7 I/O (io), D8 GND (power), D9 VCC (power), D10 I/O (io), D11 I/O (io), D12 I/O (io), D13 I/O (io), D14 VCC (power), D15 I/O (io), D16 ~{LDC}-I/O (io), E1 A7-I/O (io), E2 I/O (io), E3 A10-I/O (io), E14 HDC-I/O (io), E15 I/O (io), E16 I/O (io), F1 I/O (io), F2 A12-I/O (io), F3 I/O (io), F14 I/O (io), F15 I/O (io), F16 I/O (io), G1 I/O (io), G2 I/O (io), G3 I/O (io), G14 I/O (io), G15 I/O (io), G16 I/O (io), H1 A6-I/O (io), H2 A13-I/O (io), H3 VCC (power), H14 VCC (power), H15 ~{INIT}-I/O (io), H16 I/O (io), J1 I/O (io), J2 I/O (io), J3 GND (power), J14 GND (power), J15 I/O (io), J16 I/O (io), K1 A5-I/O (io), K2 A14-I/O (io), K3 I/O (io), K14 I/O (io), K15 I/O (io), K16 I/O (io), L1 I/O (io), L2 A4-I/O (io), L3 I/O (io), L14 I/O (io), L15 I/O (io), L16 I/O (io), M1 A15-I/O (io), M2 I/O (io), M3 A1-CS2-I/O (io), M14 I/O (io), M15 I/O (io), M16 I/O (io), N1 A3-I/O (io), N2 I/O (io), N3 GND (power), N4 DOUT-I/O (io), N5 I/O (io), N6 I/O (io), N7 I/O (io), N8 GND (power), N9 VCC (power), N10 I/O (io), N11 I/O (io), N12 I/O (io), N13 D7-I/O (io), N14 GND (power), N15 I/O (io), N16 I/O (io), P1 A2-I/O (io), P2 A0-~{WS}-I/O (io), P3 VCC (power), P4 I/O (io), P5 RDY/~{BUSY}-~{BCLK}-I/O (io), P6 I/O (io), P7 I/O (io), P8 D3-I/O (io), P9 I/O (io), P10 I/O (io), P11 I/O (io), P12 D6-I/O (io), P13 I/O (io), P14 VCC (power), P15 XTAL2(IN)-I/O (io), P16 I/O (io), R1 I/O (io), R2 CCLK (io), R3 D0-DIN-I/O (io), R4 I/O (io), R5 D1-I/O (io), R6 I/O (io), R7 D2-I/O (io), R8 ~{CS1}-I/O (io), R9 D4-I/O (io), R10 ~{CS0}-I/O (io), R11 I/O (io), R12 I/O (io), R13 I/O (io), R14 DONE-~{PG} (out), R15 ~{RESET} (in), R16 I/O (io), T1 N/C, T2 N/C, T3 N/C, T4 I/O (io), T5 I/O (io), T6 I/O (io), T7 I/O (io), T8 I/O (io), T9 I/O (io), T10 I/O (io), T11 D5-I/O (io), T12 I/O (io), T13 I/O (io), T14 BCLKIN-XTAL1(OUT)-I/O (io), T15 N/C, T16 N/C

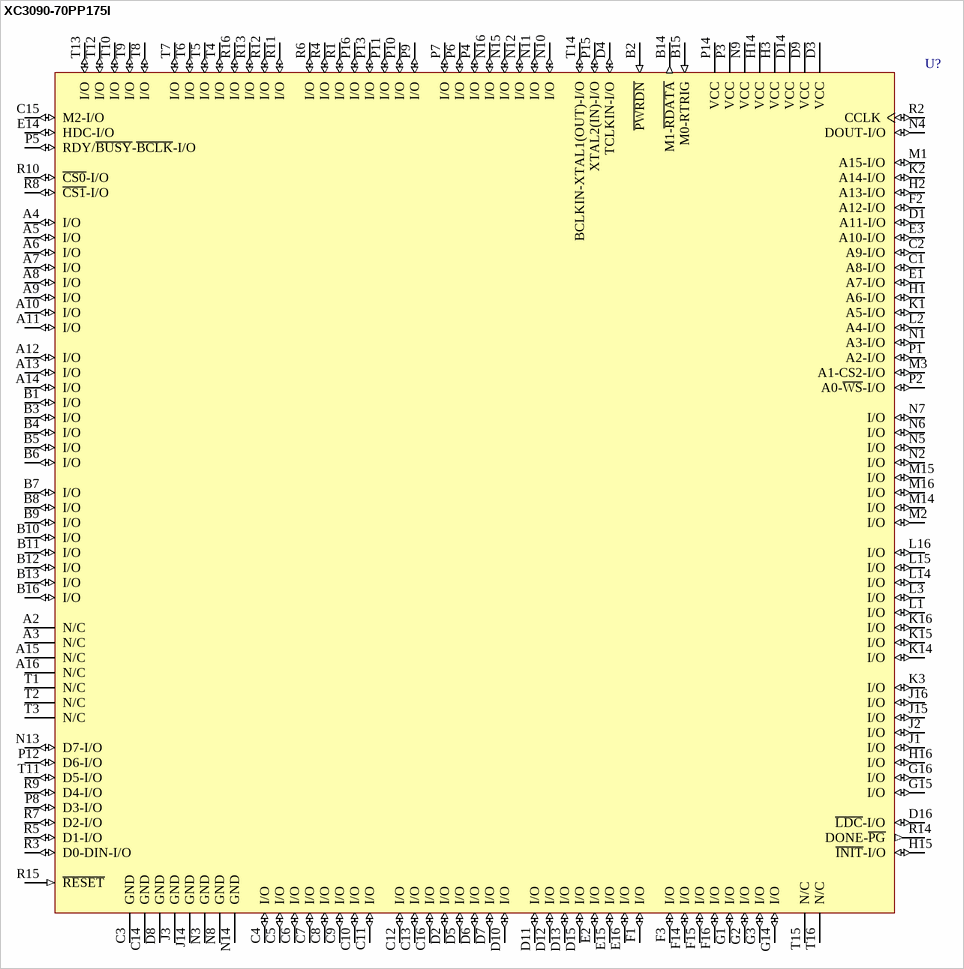
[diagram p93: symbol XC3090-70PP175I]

## XC3090-70PP175I
designator U?
Logic Cell Array with 320 CLBs, with 144 I/O Pins, 175-Pin PGA, Industrial Grade; ComponentAvailability: Not for New Design
footprint PP175 (PGA, 175-Leads, Body 42x42mm, Pitch 2.54mm)
3D model XC3090-PP175 (175-Pin Plastic Pin Grid Array (PP175))
pins: A2 N/C, A3 N/C, A4 I/O (io), A5 I/O (io), A6 I/O (io), A7 I/O (io), A8 I/O (io), A9 I/O (io), A10 I/O (io), A11 I/O (io), A12 I/O (io), A13 I/O (io), A14 I/O (io), A15 N/C, A16 N/C, B1 I/O (io), B2 ~{PWRDN} (in), B3 I/O (io), B4 I/O (io), B5 I/O (io), B6 I/O (io), B7 I/O (io), B8 I/O (io), B9 I/O (io), B10 I/O (io), B11 I/O (io), B12 I/O (io), B13 I/O (io), B14 M1-~{RDATA} (out), B15 M0-RTRIG (in), B16 I/O (io), C1 A8-I/O (io), C2 A9-I/O (io), C3 GND (power), C4 I/O (io), C5 I/O (io), C6 I/O (io), C7 I/O (io), C8 I/O (io), C9 I/O (io), C10 I/O (io), C11 I/O (io), C12 I/O (io), C13 I/O (io), C14 GND (power), C15 M2-I/O (io), C16 I/O (io), D1 A11-I/O (io), D2 I/O (io), D3 VCC (power), D4 TCLKIN-I/O (io), D5 I/O (io), D6 I/O (io), D7 I/O (io), D8 GND (power), D9 VCC (power), D10 I/O (io), D11 I/O (io), D12 I/O (io), D13 I/O (io), D14 VCC (power), D15 I/O (io), D16 ~{LDC}-I/O (io), E1 A7-I/O (io), E2 I/O (io), E3 A10-I/O (io), E14 HDC-I/O (io), E15 I/O (io), E16 I/O (io), F1 I/O (io), F2 A12-I/O (io), F3 I/O (io), F14 I/O (io), F15 I/O (io), F16 I/O (io), G1 I/O (io), G2 I/O (io), G3 I/O (io), G14 I/O (io), G15 I/O (io), G16 I/O (io), H1 A6-I/O (io), H2 A13-I/O (io), H3 VCC (power), H14 VCC (power), H15 ~{INIT}-I/O (io), H16 I/O (io), J1 I/O (io), J2 I/O (io), J3 GND (power), J14 GND (power), J15 I/O (io), J16 I/O (io), K1 A5-I/O (io), K2 A14-I/O (io), K3 I/O (io), K14 I/O (io), K15 I/O (io), K16 I/O (io), L1 I/O (io), L2 A4-I/O (io), L3 I/O (io), L14 I/O (io), L15 I/O (io), L16 I/O (io), M1 A15-I/O (io), M2 I/O (io), M3 A1-CS2-I/O (io), M14 I/O (io), M15 I/O (io), M16 I/O (io), N1 A3-I/O (io), N2 I/O (io), N3 GND (power), N4 DOUT-I/O (io), N5 I/O (io), N6 I/O (io), N7 I/O (io), N8 GND (power), N9 VCC (power), N10 I/O (io), N11 I/O (io), N12 I/O (io), N13 D7-I/O (io), N14 GND (power), N15 I/O (io), N16 I/O (io), P1 A2-I/O (io), P2 A0-~{WS}-I/O (io), P3 VCC (power), P4 I/O (io), P5 RDY/~{BUSY}-~{BCLK}-I/O (io), P6 I/O (io), P7 I/O (io), P8 D3-I/O (io), P9 I/O (io), P10 I/O (io), P11 I/O (io), P12 D6-I/O (io), P13 I/O (io), P14 VCC (power), P15 XTAL2(IN)-I/O (io), P16 I/O (io), R1 I/O (io), R2 CCLK (io), R3 D0-DIN-I/O (io), R4 I/O (io), R5 D1-I/O (io), R6 I/O (io), R7 D2-I/O (io), R8 ~{CS1}-I/O (io), R9 D4-I/O (io), R10 ~{CS0}-I/O (io), R11 I/O (io), R12 I/O (io), R13 I/O (io), R14 DONE-~{PG} (out), R15 ~{RESET} (in), R16 I/O (io), T1 N/C, T2 N/C, T3 N/C, T4 I/O (io), T5 I/O (io), T6 I/O (io), T7 I/O (io), T8 I/O (io), T9 I/O (io), T10 I/O (io), T11 D5-I/O (io), T12 I/O (io), T13 I/O (io), T14 BCLKIN-XTAL1(OUT)-I/O (io), T15 N/C, T16 N/C

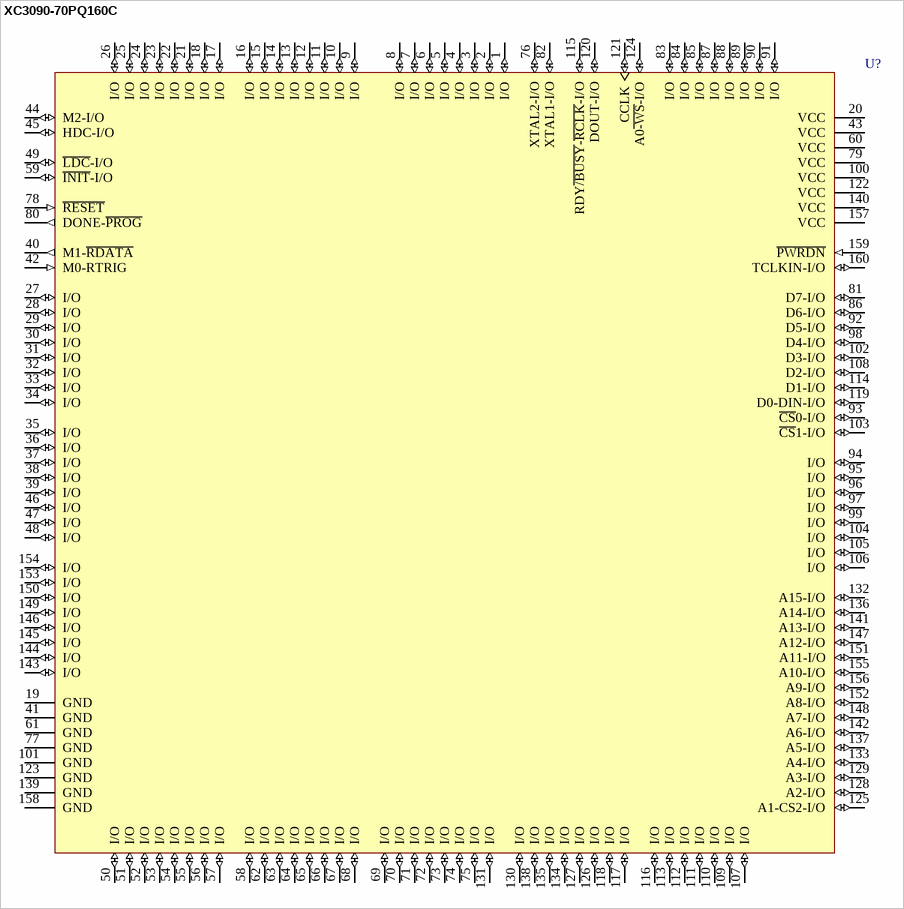
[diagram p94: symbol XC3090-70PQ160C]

## XC3090-70PQ160C
designator U?
Logic Cell Array with 320 CLBs, with 138 I/O Pins, 160-Pin PQFP, Commercial Grade; ComponentAvailability: Not for New Design
footprint PQ160_N (QFP, 160-Leads, Body 28 x 28mm, Pitch 0.65mm, IPC Medium Density)
footprint PQ160_L (QFP, 160-Leads, Body 28 x 28mm, Pitch 0.65mm, IPC High Density)
footprint PQ160_M (QFP, 160-Leads, Body 28 x 28mm, Pitch 0.65mm, IPC Low Density)
3D model XC3090-PQ160 (160-Pin Plastic Quad Flat Pack (PQ160))
pins: 1 I/O (io), 2 I/O (io), 3 I/O (io), 4 I/O (io), 5 I/O (io), 6 I/O (io), 7 I/O (io), 8 I/O (io), 9 I/O (io), 10 I/O (io), 11 I/O (io), 12 I/O (io), 13 I/O (io), 14 I/O (io), 15 I/O (io), 16 I/O (io), 17 I/O (io), 18 I/O (io), 19 GND (power), 20 VCC (power), 21 I/O (io), 22 I/O (io), 23 I/O (io), 24 I/O (io), 25 I/O (io), 26 I/O (io), 27 I/O (io), 28 I/O (io), 29 I/O (io), 30 I/O (io), 31 I/O (io), 32 I/O (io), 33 I/O (io), 34 I/O (io), 35 I/O (io), 36 I/O (io), 37 I/O (io), 38 I/O (io), 39 I/O (io), 40 M1-~{RDATA} (out), 41 GND (power), 42 M0-RTRIG (in), 43 VCC (power), 44 M2-I/O (io), 45 HDC-I/O (io), 46 I/O (io), 47 I/O (io), 48 I/O (io), 49 ~{LDC}-I/O (io), 50 I/O (io), 51 I/O (io), 52 I/O (io), 53 I/O (io), 54 I/O (io), 55 I/O (io), 56 I/O (io), 57 I/O (io), 58 I/O (io), 59 ~{INIT}-I/O (io), 60 VCC (power), 61 GND (power), 62 I/O (io), 63 I/O (io), 64 I/O (io), 65 I/O (io), 66 I/O (io), 67 I/O (io), 68 I/O (io), 69 I/O (io), 70 I/O (io), 71 I/O (io), 72 I/O (io), 73 I/O (io), 74 I/O (io), 75 I/O (io), 76 XTAL2-I/O (io), 77 GND (power), 78 ~{RESET} (in), 79 VCC (power), 80 DONE-~{PROG} (out), 81 D7-I/O (io), 82 XTAL1-I/O (io), 83 I/O (io), 84 I/O (io), 85 I/O (io), 86 D6-I/O (io), 87 I/O (io), 88 I/O (io), 89 I/O (io), 90 I/O (io), 91 I/O (io), 92 D5-I/O (io), 93 ~{CS}0-I/O (io), 94 I/O (io), 95 I/O (io), 96 I/O (io), 97 I/O (io), 98 D4-I/O (io), 99 I/O (io), 100 VCC (power), 101 GND (power), 102 D3-I/O (io), 103 ~{CS}1-I/O (io), 104 I/O (io), 105 I/O (io), 106 I/O (io), 107 I/O (io), 108 D2-I/O (io), 109 I/O (io), 110 I/O (io), 111 I/O (io), 112 I/O (io), 113 I/O (io), 114 D1-I/O (io), 115 RDY~{/BUSY}-~{RCLK}-I/O (io), 116 I/O (io), 117 I/O (io), 118 I/O (io), 119 D0-DIN-I/O (io), 120 DOUT-I/O (io), 121 CCLK (io), 122 VCC (power), 123 GND (power), 124 A0~{-WS}-I/O (io), 125 A1-CS2-I/O (io), 126 I/O (io), 127 I/O (io), 128 A2-I/O (io), 129 A3-I/O (io), 130 I/O (io), 131 I/O (io), 132 A15-I/O (io), 133 A4-I/O (io), 134 I/O (io), 135 I/O (io), 136 A14-I/O (io), 137 A5-I/O (io), 138 I/O (io), 139 GND (power), 140 VCC (power), 141 A13-I/O (io), 142 A6-I/O (io), 143 I/O (io), 144 I/O (io), 145 I/O (io), 146 I/O (io), 147 A12-I/O (io), 148 A7-I/O (io), 149 I/O (io), 150 I/O (io), 151 A11-I/O (io), 152 A8-I/O (io), 153 I/O (io), 154 I/O (io), 155 A10-I/O (io), 156 A9-I/O (io), 157 VCC (power), 158 GND (power), 159 ~{PWRDN} (in), 160 TCLKIN-I/O (io)

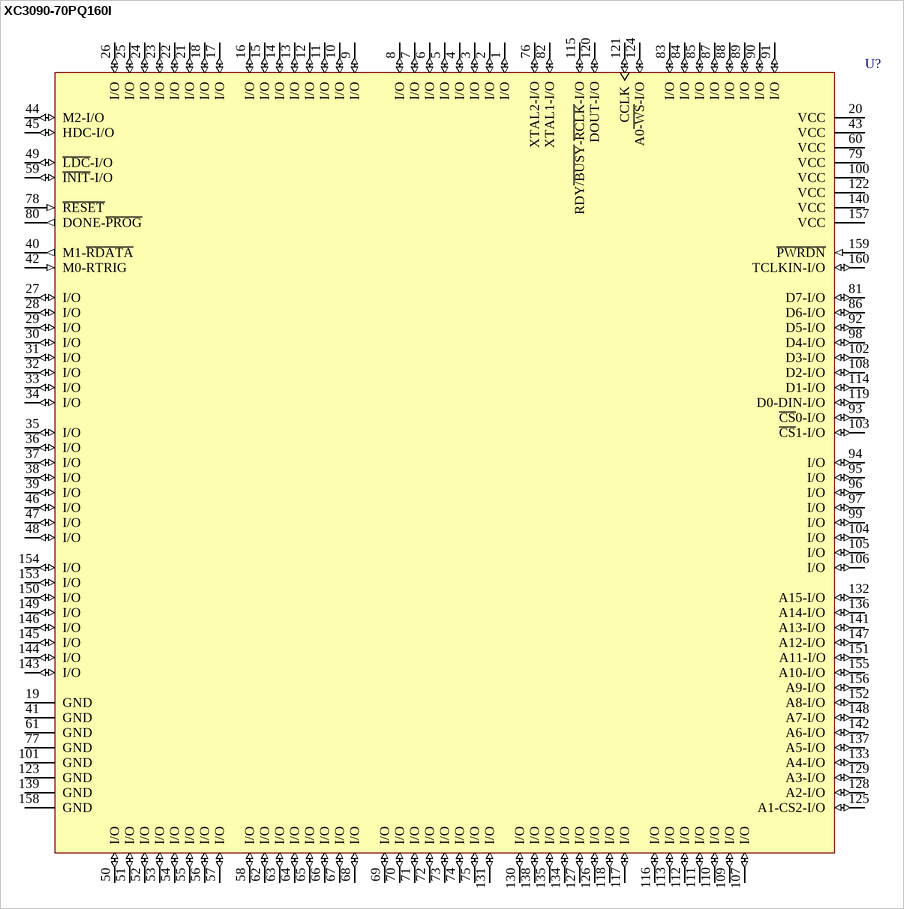
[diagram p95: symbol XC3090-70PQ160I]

## XC3090-70PQ160I
designator U?
Logic Cell Array with 320 CLBs, with 138 I/O Pins, 160-Pin PQFP, Industrial Grade; ComponentAvailability: Not for New Design
footprint PQ160_N (QFP, 160-Leads, Body 28 x 28mm, Pitch 0.65mm, IPC Medium Density)
footprint PQ160_L (QFP, 160-Leads, Body 28 x 28mm, Pitch 0.65mm, IPC High Density)
footprint PQ160_M (QFP, 160-Leads, Body 28 x 28mm, Pitch 0.65mm, IPC Low Density)
3D model XC3090-PQ160 (160-Pin Plastic Quad Flat Pack (PQ160))
pins: 1 I/O (io), 2 I/O (io), 3 I/O (io), 4 I/O (io), 5 I/O (io), 6 I/O (io), 7 I/O (io), 8 I/O (io), 9 I/O (io), 10 I/O (io), 11 I/O (io), 12 I/O (io), 13 I/O (io), 14 I/O (io), 15 I/O (io), 16 I/O (io), 17 I/O (io), 18 I/O (io), 19 GND (power), 20 VCC (power), 21 I/O (io), 22 I/O (io), 23 I/O (io), 24 I/O (io), 25 I/O (io), 26 I/O (io), 27 I/O (io), 28 I/O (io), 29 I/O (io), 30 I/O (io), 31 I/O (io), 32 I/O (io), 33 I/O (io), 34 I/O (io), 35 I/O (io), 36 I/O (io), 37 I/O (io), 38 I/O (io), 39 I/O (io), 40 M1-~{RDATA} (out), 41 GND (power), 42 M0-RTRIG (in), 43 VCC (power), 44 M2-I/O (io), 45 HDC-I/O (io), 46 I/O (io), 47 I/O (io), 48 I/O (io), 49 ~{LDC}-I/O (io), 50 I/O (io), 51 I/O (io), 52 I/O (io), 53 I/O (io), 54 I/O (io), 55 I/O (io), 56 I/O (io), 57 I/O (io), 58 I/O (io), 59 ~{INIT}-I/O (io), 60 VCC (power), 61 GND (power), 62 I/O (io), 63 I/O (io), 64 I/O (io), 65 I/O (io), 66 I/O (io), 67 I/O (io), 68 I/O (io), 69 I/O (io), 70 I/O (io), 71 I/O (io), 72 I/O (io), 73 I/O (io), 74 I/O (io), 75 I/O (io), 76 XTAL2-I/O (io), 77 GND (power), 78 ~{RESET} (in), 79 VCC (power), 80 DONE-~{PROG} (out), 81 D7-I/O (io), 82 XTAL1-I/O (io), 83 I/O (io), 84 I/O (io), 85 I/O (io), 86 D6-I/O (io), 87 I/O (io), 88 I/O (io), 89 I/O (io), 90 I/O (io), 91 I/O (io), 92 D5-I/O (io), 93 ~{CS}0-I/O (io), 94 I/O (io), 95 I/O (io), 96 I/O (io), 97 I/O (io), 98 D4-I/O (io), 99 I/O (io), 100 VCC (power), 101 GND (power), 102 D3-I/O (io), 103 ~{CS}1-I/O (io), 104 I/O (io), 105 I/O (io), 106 I/O (io), 107 I/O (io), 108 D2-I/O (io), 109 I/O (io), 110 I/O (io), 111 I/O (io), 112 I/O (io), 113 I/O (io), 114 D1-I/O (io), 115 RDY~{/BUSY}-~{RCLK}-I/O (io), 116 I/O (io), 117 I/O (io), 118 I/O (io), 119 D0-DIN-I/O (io), 120 DOUT-I/O (io), 121 CCLK (io), 122 VCC (power), 123 GND (power), 124 A0~{-WS}-I/O (io), 125 A1-CS2-I/O (io), 126 I/O (io), 127 I/O (io), 128 A2-I/O (io), 129 A3-I/O (io), 130 I/O (io), 131 I/O (io), 132 A15-I/O (io), 133 A4-I/O (io), 134 I/O (io), 135 I/O (io), 136 A14-I/O (io), 137 A5-I/O (io), 138 I/O (io), 139 GND (power), 140 VCC (power), 141 A13-I/O (io), 142 A6-I/O (io), 143 I/O (io), 144 I/O (io), 145 I/O (io), 146 I/O (io), 147 A12-I/O (io), 148 A7-I/O (io), 149 I/O (io), 150 I/O (io), 151 A11-I/O (io), 152 A8-I/O (io), 153 I/O (io), 154 I/O (io), 155 A10-I/O (io), 156 A9-I/O (io), 157 VCC (power), 158 GND (power), 159 ~{PWRDN} (in), 160 TCLKIN-I/O (io)

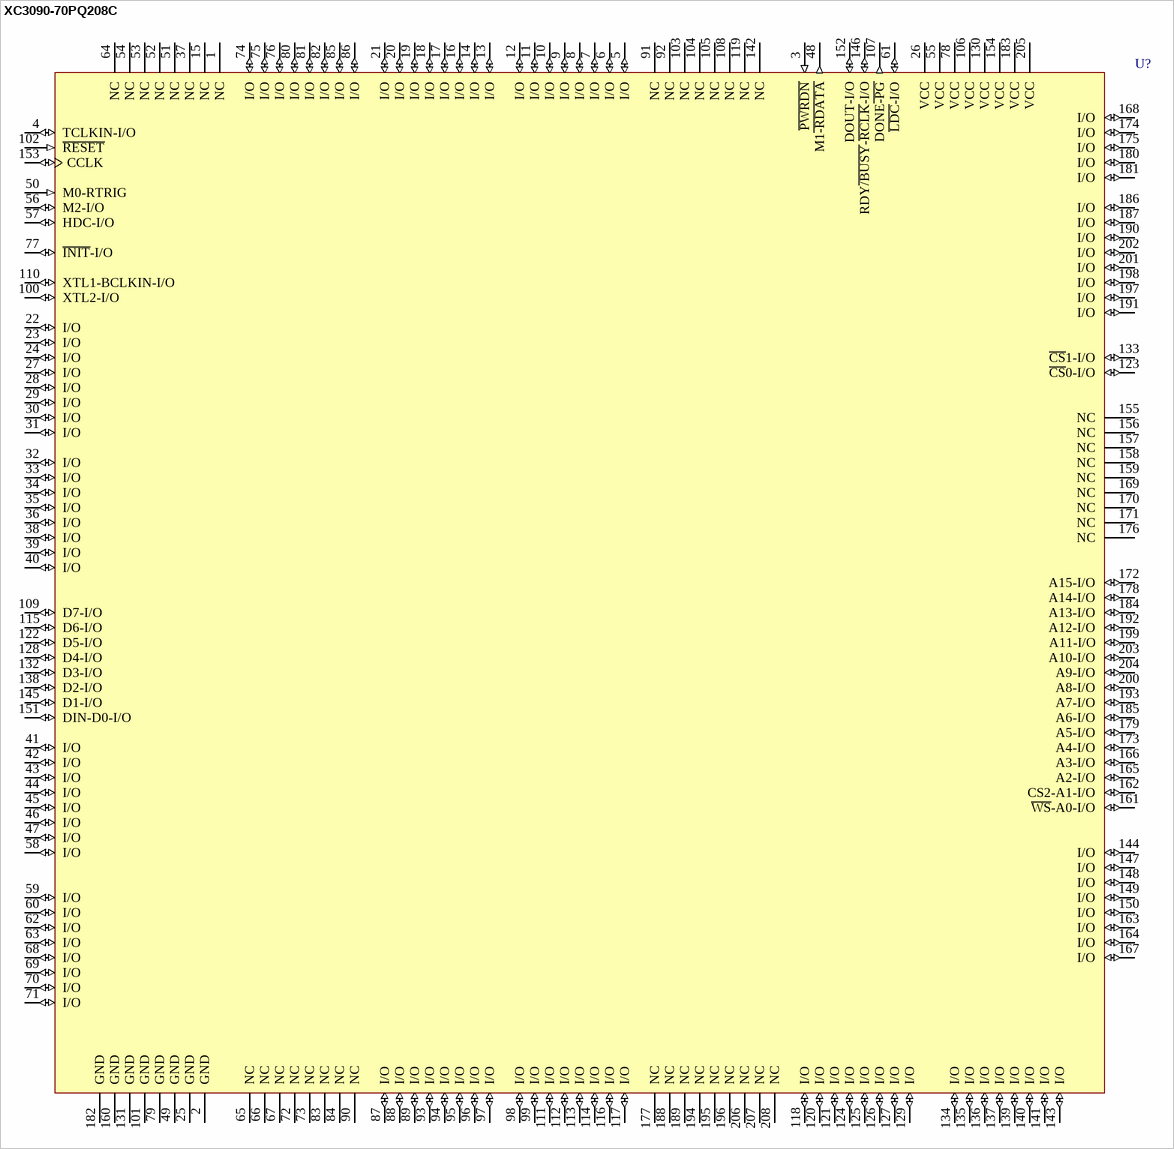
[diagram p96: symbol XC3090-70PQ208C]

## XC3090-70PQ208C
designator U?
Logic Cell Array with 320 CLBs, with 144 I/O Pins, 208-Pin PQFP, Commercial Grade; ComponentAvailability: Not for New Design
footprint PQ208_N (Shrink QFP, 208-Leads, Body 28x28mm, Pitch 0.5mm, IPC Medium Density)
footprint PQ208_L (Shrink QFP, 208-Leads, Body 28x28mm, Pitch 0.5mm, IPC High Density)
footprint PQ208_M (Shrink QFP, 208-Leads, Body 28x28mm, Pitch 0.5mm, IPC Low Density)
3D model XC3090-PQ208 (208-Pin Plastic Quad Flat Pack (PQ208))
pins: 1 NC, 2 GND (power), 3 ~{PWRDN} (in), 4 TCLKIN-I/O (io), 5 I/O (io), 6 I/O (io), 7 I/O (io), 8 I/O (io), 9 I/O (io), 10 I/O (io), 11 I/O (io), 12 I/O (io), 13 I/O (io), 14 I/O (io), 15 NC, 16 I/O (io), 17 I/O (io), 18 I/O (io), 19 I/O (io), 20 I/O (io), 21 I/O (io), 22 I/O (io), 23 I/O (io), 24 I/O (io), 25 GND (power), 26 VCC (power), 27 I/O (io), 28 I/O (io), 29 I/O (io), 30 I/O (io), 31 I/O (io), 32 I/O (io), 33 I/O (io), 34 I/O (io), 35 I/O (io), 36 I/O (io), 37 NC, 38 I/O (io), 39 I/O (io), 40 I/O (io), 41 I/O (io), 42 I/O (io), 43 I/O (io), 44 I/O (io), 45 I/O (io), 46 I/O (io), 47 I/O (io), 48 M1~{-RDATA} (out), 49 GND (power), 50 M0-RTRIG (in), 51 NC, 52 NC, 53 NC, 54 NC, 55 VCC (power), 56 M2-I/O (io), 57 HDC-I/O (io), 58 I/O (io), 59 I/O (io), 60 I/O (io), 61 ~{LDC}-I/O (io), 62 I/O (io), 63 I/O (io), 64 NC, 65 NC, 66 NC, 67 NC, 68 I/O (io), 69 I/O (io), 70 I/O (io), 71 I/O (io), 72 NC, 73 NC, 74 I/O (io), 75 I/O (io), 76 I/O (io), 77 ~{INIT}-I/O (io), 78 VCC (power), 79 GND (power), 80 I/O (io), 81 I/O (io), 82 I/O (io), 83 NC, 84 NC, 85 I/O (io), 86 I/O (io), 87 I/O (io), 88 I/O (io), 89 I/O (io), 90 NC, 91 NC, 92 NC, 93 I/O (io), 94 I/O (io), 95 I/O (io), 96 I/O (io), 97 I/O (io), 98 I/O (io), 99 I/O (io), 100 XTL2-I/O (io), 101 GND (power), 102 ~{RESET} (in), 103 NC, 104 NC, 105 NC, 106 VCC (power), 107 DONE~{-PG} (out), 108 NC, 109 D7-I/O (io), 110 XTL1-BCLKIN-I/O (io), 111 I/O (io), 112 I/O (io), 113 I/O (io), 114 I/O (io), 115 D6-I/O (io), 116 I/O (io), 117 I/O (io), 118 I/O (io), 119 NC, 120 I/O (io), 121 I/O (io), 122 D5-I/O (io), 123 ~{CS}0-I/O (io), 124 I/O (io), 125 I/O (io), 126 I/O (io), 127 I/O (io), 128 D4-I/O (io), 129 I/O (io), 130 VCC (power), 131 GND (power), 132 D3-I/O (io), 133 ~{CS}1-I/O (io), 134 I/O (io), 135 I/O (io), 136 I/O (io), 137 I/O (io), 138 D2-I/O (io), 139 I/O (io), 140 I/O (io), 141 I/O (io), 142 NC, 143 I/O (io), 144 I/O (io), 145 D1-I/O (io), 146 RDY~{/BUSY}-~{RCLK}-I/O (io), 147 I/O (io), 148 I/O (io), 149 I/O (io), 150 I/O (io), 151 DIN-D0-I/O (io), 152 DOUT-I/O (io), 153 CCLK (io), 154 VCC (power), 155 NC, 156 NC, 157 NC, 158 NC, 159 NC, 160 GND (power), 161 ~{WS}-A0-I/O (io), 162 CS2-A1-I/O (io), 163 I/O (io), 164 I/O (io), 165 A2-I/O (io), 166 A3-I/O (io), 167 I/O (io), 168 I/O (io), 169 NC, 170 NC, 171 NC, 172 A15-I/O (io), 173 A4-I/O (io), 174 I/O (io), 175 I/O (io), 176 NC, 177 NC, 178 A14-I/O (io), 179 A5-I/O (io), 180 I/O (io), 181 I/O (io), 182 GND (power), 183 VCC (power), 184 A13-I/O (io), 185 A6-I/O (io), 186 I/O (io), 187 I/O (io), 188 NC, 189 NC, 190 I/O (io), 191 I/O (io), 192 A12-I/O (io), 193 A7-I/O (io), 194 NC, 195 NC, 196 NC, 197 I/O (io), 198 I/O (io), 199 A11-I/O (io), 200 A8-I/O (io), 201 I/O (io), 202 I/O (io), 203 A10-I/O (io), 204 A9-I/O (io), 205 VCC (power), 206 NC, 207 NC, 208 NC

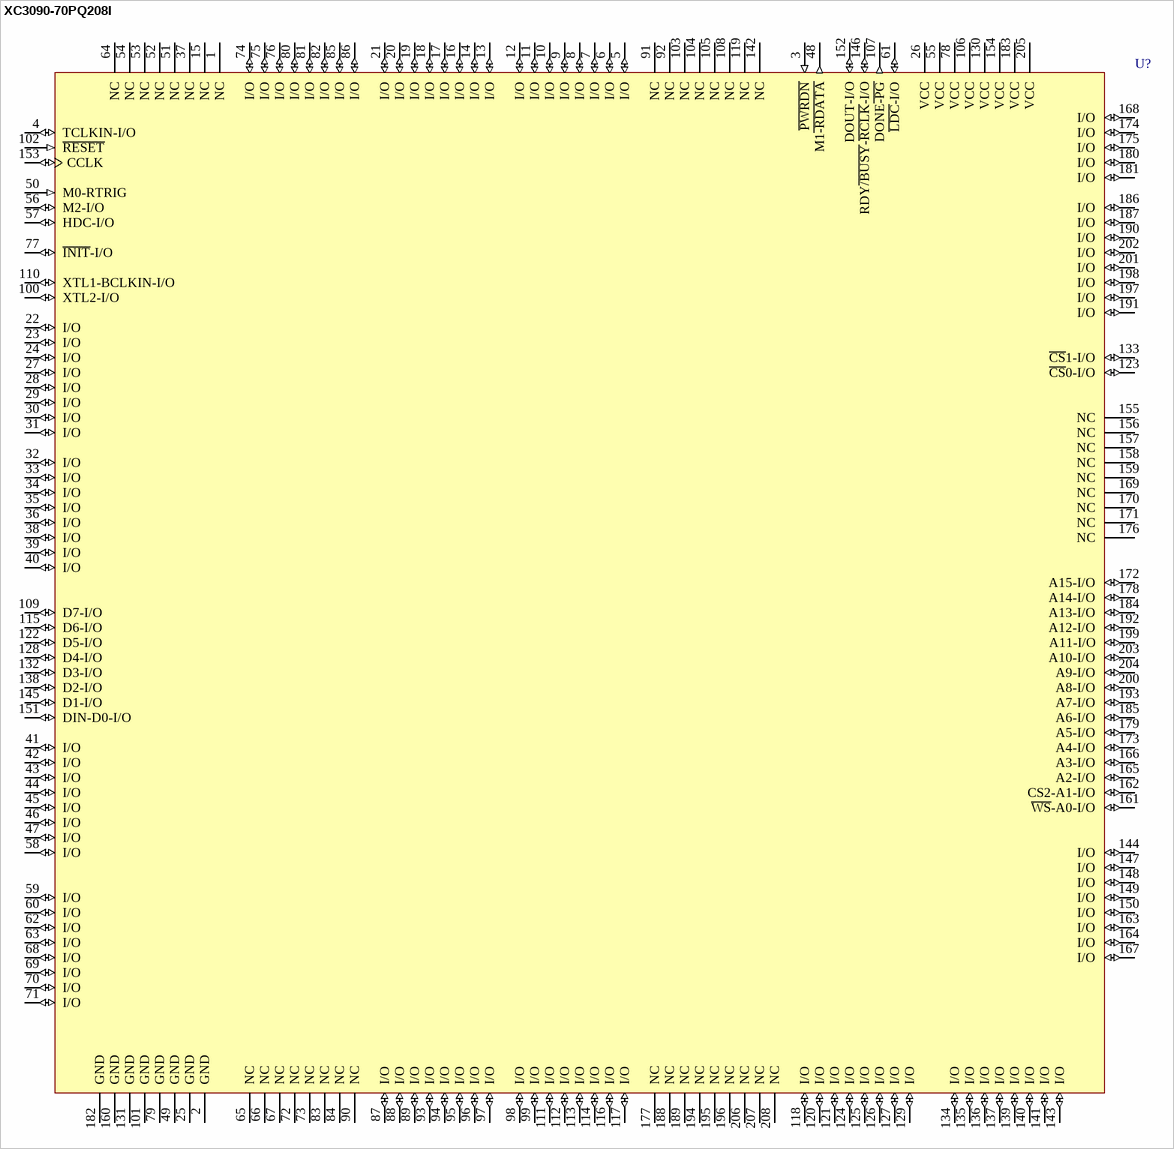
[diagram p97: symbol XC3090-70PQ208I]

## XC3090-70PQ208I
designator U?
Logic Cell Array with 320 CLBs, with 144 I/O Pins, 208-Pin PQFP, Industrial Grade; ComponentAvailability: Not for New Design
footprint PQ208_N (Shrink QFP, 208-Leads, Body 28x28mm, Pitch 0.5mm, IPC Medium Density)
footprint PQ208_L (Shrink QFP, 208-Leads, Body 28x28mm, Pitch 0.5mm, IPC High Density)
footprint PQ208_M (Shrink QFP, 208-Leads, Body 28x28mm, Pitch 0.5mm, IPC Low Density)
3D model XC3090-PQ208 (208-Pin Plastic Quad Flat Pack (PQ208))
pins: 1 NC, 2 GND (power), 3 ~{PWRDN} (in), 4 TCLKIN-I/O (io), 5 I/O (io), 6 I/O (io), 7 I/O (io), 8 I/O (io), 9 I/O (io), 10 I/O (io), 11 I/O (io), 12 I/O (io), 13 I/O (io), 14 I/O (io), 15 NC, 16 I/O (io), 17 I/O (io), 18 I/O (io), 19 I/O (io), 20 I/O (io), 21 I/O (io), 22 I/O (io), 23 I/O (io), 24 I/O (io), 25 GND (power), 26 VCC (power), 27 I/O (io), 28 I/O (io), 29 I/O (io), 30 I/O (io), 31 I/O (io), 32 I/O (io), 33 I/O (io), 34 I/O (io), 35 I/O (io), 36 I/O (io), 37 NC, 38 I/O (io), 39 I/O (io), 40 I/O (io), 41 I/O (io), 42 I/O (io), 43 I/O (io), 44 I/O (io), 45 I/O (io), 46 I/O (io), 47 I/O (io), 48 M1~{-RDATA} (out), 49 GND (power), 50 M0-RTRIG (in), 51 NC, 52 NC, 53 NC, 54 NC, 55 VCC (power), 56 M2-I/O (io), 57 HDC-I/O (io), 58 I/O (io), 59 I/O (io), 60 I/O (io), 61 ~{LDC}-I/O (io), 62 I/O (io), 63 I/O (io), 64 NC, 65 NC, 66 NC, 67 NC, 68 I/O (io), 69 I/O (io), 70 I/O (io), 71 I/O (io), 72 NC, 73 NC, 74 I/O (io), 75 I/O (io), 76 I/O (io), 77 ~{INIT}-I/O (io), 78 VCC (power), 79 GND (power), 80 I/O (io), 81 I/O (io), 82 I/O (io), 83 NC, 84 NC, 85 I/O (io), 86 I/O (io), 87 I/O (io), 88 I/O (io), 89 I/O (io), 90 NC, 91 NC, 92 NC, 93 I/O (io), 94 I/O (io), 95 I/O (io), 96 I/O (io), 97 I/O (io), 98 I/O (io), 99 I/O (io), 100 XTL2-I/O (io), 101 GND (power), 102 ~{RESET} (in), 103 NC, 104 NC, 105 NC, 106 VCC (power), 107 DONE~{-PG} (out), 108 NC, 109 D7-I/O (io), 110 XTL1-BCLKIN-I/O (io), 111 I/O (io), 112 I/O (io), 113 I/O (io), 114 I/O (io), 115 D6-I/O (io), 116 I/O (io), 117 I/O (io), 118 I/O (io), 119 NC, 120 I/O (io), 121 I/O (io), 122 D5-I/O (io), 123 ~{CS}0-I/O (io), 124 I/O (io), 125 I/O (io), 126 I/O (io), 127 I/O (io), 128 D4-I/O (io), 129 I/O (io), 130 VCC (power), 131 GND (power), 132 D3-I/O (io), 133 ~{CS}1-I/O (io), 134 I/O (io), 135 I/O (io), 136 I/O (io), 137 I/O (io), 138 D2-I/O (io), 139 I/O (io), 140 I/O (io), 141 I/O (io), 142 NC, 143 I/O (io), 144 I/O (io), 145 D1-I/O (io), 146 RDY~{/BUSY}-~{RCLK}-I/O (io), 147 I/O (io), 148 I/O (io), 149 I/O (io), 150 I/O (io), 151 DIN-D0-I/O (io), 152 DOUT-I/O (io), 153 CCLK (io), 154 VCC (power), 155 NC, 156 NC, 157 NC, 158 NC, 159 NC, 160 GND (power), 161 ~{WS}-A0-I/O (io), 162 CS2-A1-I/O (io), 163 I/O (io), 164 I/O (io), 165 A2-I/O (io), 166 A3-I/O (io), 167 I/O (io), 168 I/O (io), 169 NC, 170 NC, 171 NC, 172 A15-I/O (io), 173 A4-I/O (io), 174 I/O (io), 175 I/O (io), 176 NC, 177 NC, 178 A14-I/O (io), 179 A5-I/O (io), 180 I/O (io), 181 I/O (io), 182 GND (power), 183 VCC (power), 184 A13-I/O (io), 185 A6-I/O (io), 186 I/O (io), 187 I/O (io), 188 NC, 189 NC, 190 I/O (io), 191 I/O (io), 192 A12-I/O (io), 193 A7-I/O (io), 194 NC, 195 NC, 196 NC, 197 I/O (io), 198 I/O (io), 199 A11-I/O (io), 200 A8-I/O (io), 201 I/O (io), 202 I/O (io), 203 A10-I/O (io), 204 A9-I/O (io), 205 VCC (power), 206 NC, 207 NC, 208 NC

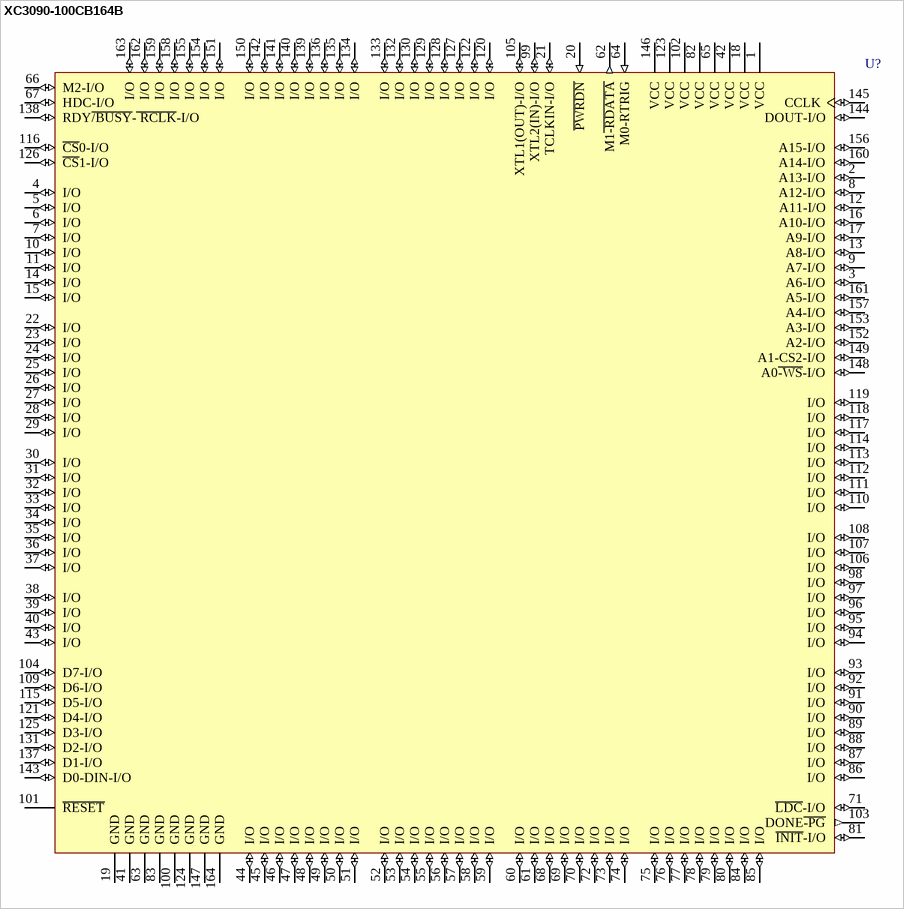
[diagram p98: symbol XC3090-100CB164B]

## XC3090-100CB164B
designator U?
Logic Cell Array with 320 CLBs, with 142 I/O Pins, 164-Pin CQFP, Military Class B Grade; ComponentAvailability: Not for New Design
footprint CB164_N (CQFP, 164-Leads, Body 29x29mm; Pitch 0.635mm, Gullwing Leadform, IPC Medium Density)
footprint CB164_L (CQFP, 164-Leads, Body 29x29mm; Pitch 0.635mm, Gullwing Leadform, IPC High Density)
footprint CB164_M (CQFP, 164-Leads, Body 29x29mm; Pitch 0.635mm, Gullwing Leadform, IPC Low Density)
3D model XC3090-CB164 (164-Pin Ceramic Brazed Quad Flat Pack (CB164))
pins: 1 VCC (power), 2 A13-I/O (io), 3 A6-I/O (io), 4 I/O (io), 5 I/O (io), 6 I/O (io), 7 I/O (io), 8 A12-I/O (io), 9 A7-I/O (io), 10 I/O (io), 11 I/O (io), 12 A11-I/O (io), 13 A8-I/O (io), 14 I/O (io), 15 I/O (io), 16 A10-I/O (io), 17 A9-I/O (io), 18 VCC (power), 19 GND (power), 20 ~{PWRDN} (in), 21 TCLKIN-I/O (io), 22 I/O (io), 23 I/O (io), 24 I/O (io), 25 I/O (io), 26 I/O (io), 27 I/O (io), 28 I/O (io), 29 I/O (io), 30 I/O (io), 31 I/O (io), 32 I/O (io), 33 I/O (io), 34 I/O (io), 35 I/O (io), 36 I/O (io), 37 I/O (io), 38 I/O (io), 39 I/O (io), 40 I/O (io), 41 GND (power), 42 VCC (power), 43 I/O (io), 44 I/O (io), 45 I/O (io), 46 I/O (io), 47 I/O (io), 48 I/O (io), 49 I/O (io), 50 I/O (io), 51 I/O (io), 52 I/O (io), 53 I/O (io), 54 I/O (io), 55 I/O (io), 56 I/O (io), 57 I/O (io), 58 I/O (io), 59 I/O (io), 60 I/O (io), 61 I/O (io), 62 M1~{-RDATA} (out), 63 GND (power), 64 M0-RTRIG (in), 65 VCC (power), 66 M2-I/O (io), 67 HDC-I/O (io), 68 I/O (io), 69 I/O (io), 70 I/O (io), 71 ~{LDC}-I/O (io), 72 I/O (io), 73 I/O (io), 74 I/O (io), 75 I/O (io), 76 I/O (io), 77 I/O (io), 78 I/O (io), 79 I/O (io), 80 I/O (io), 81 ~{INIT}-I/O (io), 82 VCC (power), 83 GND (power), 84 I/O (io), 85 I/O (io), 86 I/O (io), 87 I/O (io), 88 I/O (io), 89 I/O (io), 90 I/O (io), 91 I/O (io), 92 I/O (io), 93 I/O (io), 94 I/O (io), 95 I/O (io), 96 I/O (io), 97 I/O (io), 98 I/O (io), 99 XTL2(IN)-I/O (io), 100 GND (power), 101 ~{RESET} (oe), 102 VCC (power), 103 DONE~{-PG} (out), 104 D7-I/O (io), 105 XTL1(OUT)-I/O (io), 106 I/O (io), 107 I/O (io), 108 I/O (io), 109 D6-I/O (io), 110 I/O (io), 111 I/O (io), 112 I/O (io), 113 I/O (io), 114 I/O (io), 115 D5-I/O (io), 116 ~{CS}0-I/O (io), 117 I/O (io), 118 I/O (io), 119 I/O (io), 120 I/O (io), 121 D4-I/O (io), 122 I/O (io), 123 VCC (power), 124 GND (power), 125 D3-I/O (io), 126 ~{CS}1-I/O (io), 127 I/O (io), 128 I/O (io), 129 I/O (io), 130 I/O (io), 131 D2-I/O (io), 132 I/O (io), 133 I/O (io), 134 I/O (io), 135 I/O (io), 136 I/O (io), 137 D1-I/O (io), 138 RDY~{/BUSY}-~{ RCLK}-I/O (io), 139 I/O (io), 140 I/O (io), 141 I/O (io), 142 I/O (io), 143 D0-DIN-I/O (io), 144 DOUT-I/O (io), 145 CCLK (io), 146 VCC (power), 147 GND (power), 148 A0~{-WS}-I/O (io), 149 A1-CS2-I/O (io), 150 I/O (io), 151 I/O (io), 152 A2-I/O (io), 153 A3-I/O (io), 154 I/O (io), 155 I/O (io), 156 A15-I/O (io), 157 A4-I/O (io), 158 I/O (io), 159 I/O (io), 160 A14-I/O (io), 161 A5-I/O (io), 162 I/O (io), 163 I/O (io), 164 GND (power)

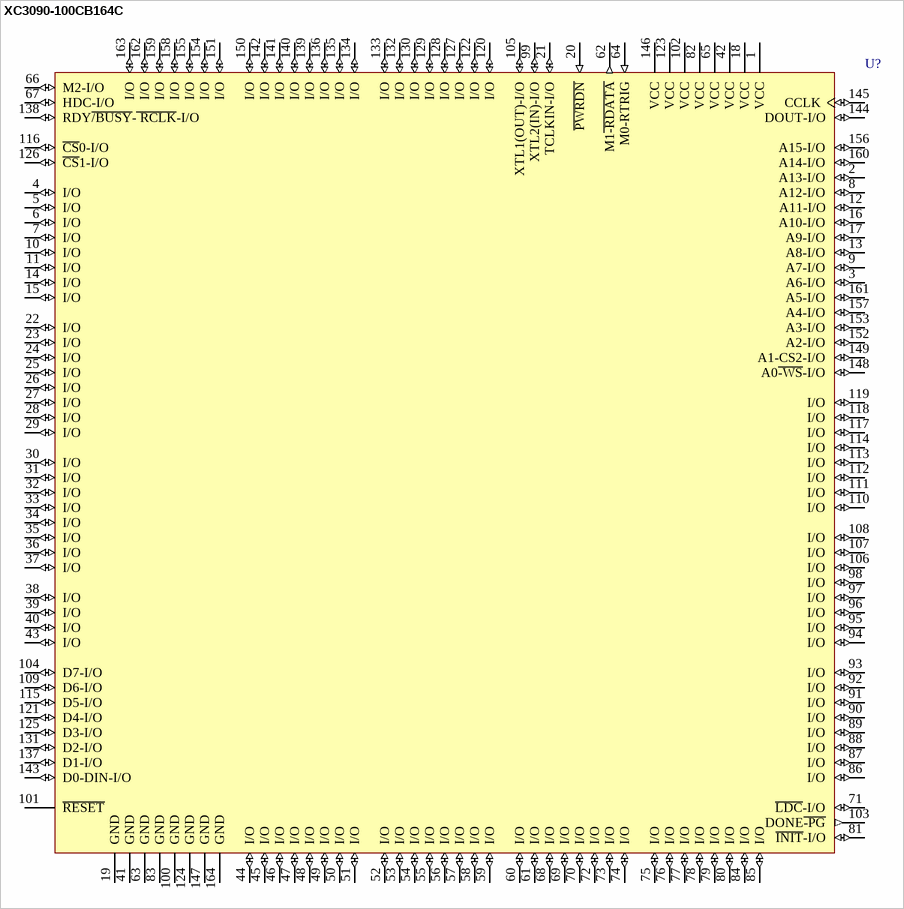
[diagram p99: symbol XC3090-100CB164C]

## XC3090-100CB164C
designator U?
Logic Cell Array with 320 CLBs, with 142 I/O Pins, 164-Pin CQFP, Commercial Grade; ComponentAvailability: Not for New Design
footprint CB164_N (CQFP, 164-Leads, Body 29x29mm; Pitch 0.635mm, Gullwing Leadform, IPC Medium Density)
footprint CB164_L (CQFP, 164-Leads, Body 29x29mm; Pitch 0.635mm, Gullwing Leadform, IPC High Density)
footprint CB164_M (CQFP, 164-Leads, Body 29x29mm; Pitch 0.635mm, Gullwing Leadform, IPC Low Density)
3D model XC3090-CB164 (164-Pin Ceramic Brazed Quad Flat Pack (CB164))
pins: 1 VCC (power), 2 A13-I/O (io), 3 A6-I/O (io), 4 I/O (io), 5 I/O (io), 6 I/O (io), 7 I/O (io), 8 A12-I/O (io), 9 A7-I/O (io), 10 I/O (io), 11 I/O (io), 12 A11-I/O (io), 13 A8-I/O (io), 14 I/O (io), 15 I/O (io), 16 A10-I/O (io), 17 A9-I/O (io), 18 VCC (power), 19 GND (power), 20 ~{PWRDN} (in), 21 TCLKIN-I/O (io), 22 I/O (io), 23 I/O (io), 24 I/O (io), 25 I/O (io), 26 I/O (io), 27 I/O (io), 28 I/O (io), 29 I/O (io), 30 I/O (io), 31 I/O (io), 32 I/O (io), 33 I/O (io), 34 I/O (io), 35 I/O (io), 36 I/O (io), 37 I/O (io), 38 I/O (io), 39 I/O (io), 40 I/O (io), 41 GND (power), 42 VCC (power), 43 I/O (io), 44 I/O (io), 45 I/O (io), 46 I/O (io), 47 I/O (io), 48 I/O (io), 49 I/O (io), 50 I/O (io), 51 I/O (io), 52 I/O (io), 53 I/O (io), 54 I/O (io), 55 I/O (io), 56 I/O (io), 57 I/O (io), 58 I/O (io), 59 I/O (io), 60 I/O (io), 61 I/O (io), 62 M1~{-RDATA} (out), 63 GND (power), 64 M0-RTRIG (in), 65 VCC (power), 66 M2-I/O (io), 67 HDC-I/O (io), 68 I/O (io), 69 I/O (io), 70 I/O (io), 71 ~{LDC}-I/O (io), 72 I/O (io), 73 I/O (io), 74 I/O (io), 75 I/O (io), 76 I/O (io), 77 I/O (io), 78 I/O (io), 79 I/O (io), 80 I/O (io), 81 ~{INIT}-I/O (io), 82 VCC (power), 83 GND (power), 84 I/O (io), 85 I/O (io), 86 I/O (io), 87 I/O (io), 88 I/O (io), 89 I/O (io), 90 I/O (io), 91 I/O (io), 92 I/O (io), 93 I/O (io), 94 I/O (io), 95 I/O (io), 96 I/O (io), 97 I/O (io), 98 I/O (io), 99 XTL2(IN)-I/O (io), 100 GND (power), 101 ~{RESET} (oe), 102 VCC (power), 103 DONE~{-PG} (out), 104 D7-I/O (io), 105 XTL1(OUT)-I/O (io), 106 I/O (io), 107 I/O (io), 108 I/O (io), 109 D6-I/O (io), 110 I/O (io), 111 I/O (io), 112 I/O (io), 113 I/O (io), 114 I/O (io), 115 D5-I/O (io), 116 ~{CS}0-I/O (io), 117 I/O (io), 118 I/O (io), 119 I/O (io), 120 I/O (io), 121 D4-I/O (io), 122 I/O (io), 123 VCC (power), 124 GND (power), 125 D3-I/O (io), 126 ~{CS}1-I/O (io), 127 I/O (io), 128 I/O (io), 129 I/O (io), 130 I/O (io), 131 D2-I/O (io), 132 I/O (io), 133 I/O (io), 134 I/O (io), 135 I/O (io), 136 I/O (io), 137 D1-I/O (io), 138 RDY~{/BUSY}-~{ RCLK}-I/O (io), 139 I/O (io), 140 I/O (io), 141 I/O (io), 142 I/O (io), 143 D0-DIN-I/O (io), 144 DOUT-I/O (io), 145 CCLK (io), 146 VCC (power), 147 GND (power), 148 A0~{-WS}-I/O (io), 149 A1-CS2-I/O (io), 150 I/O (io), 151 I/O (io), 152 A2-I/O (io), 153 A3-I/O (io), 154 I/O (io), 155 I/O (io), 156 A15-I/O (io), 157 A4-I/O (io), 158 I/O (io), 159 I/O (io), 160 A14-I/O (io), 161 A5-I/O (io), 162 I/O (io), 163 I/O (io), 164 GND (power)

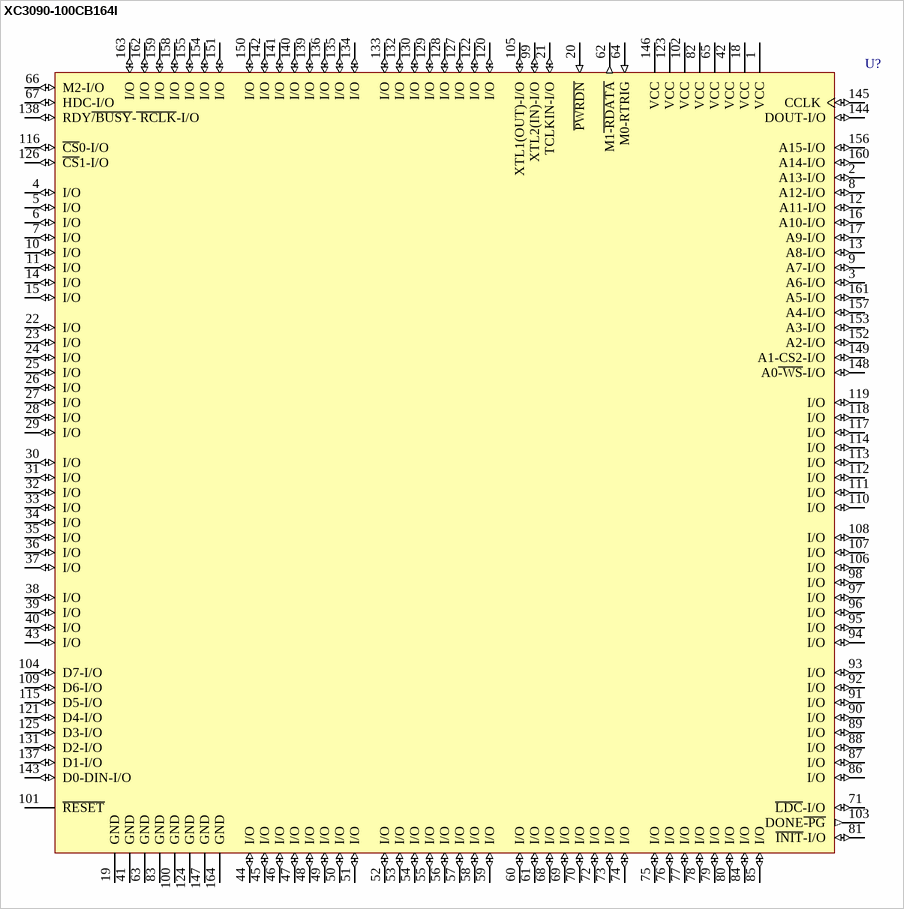
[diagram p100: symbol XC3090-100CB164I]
